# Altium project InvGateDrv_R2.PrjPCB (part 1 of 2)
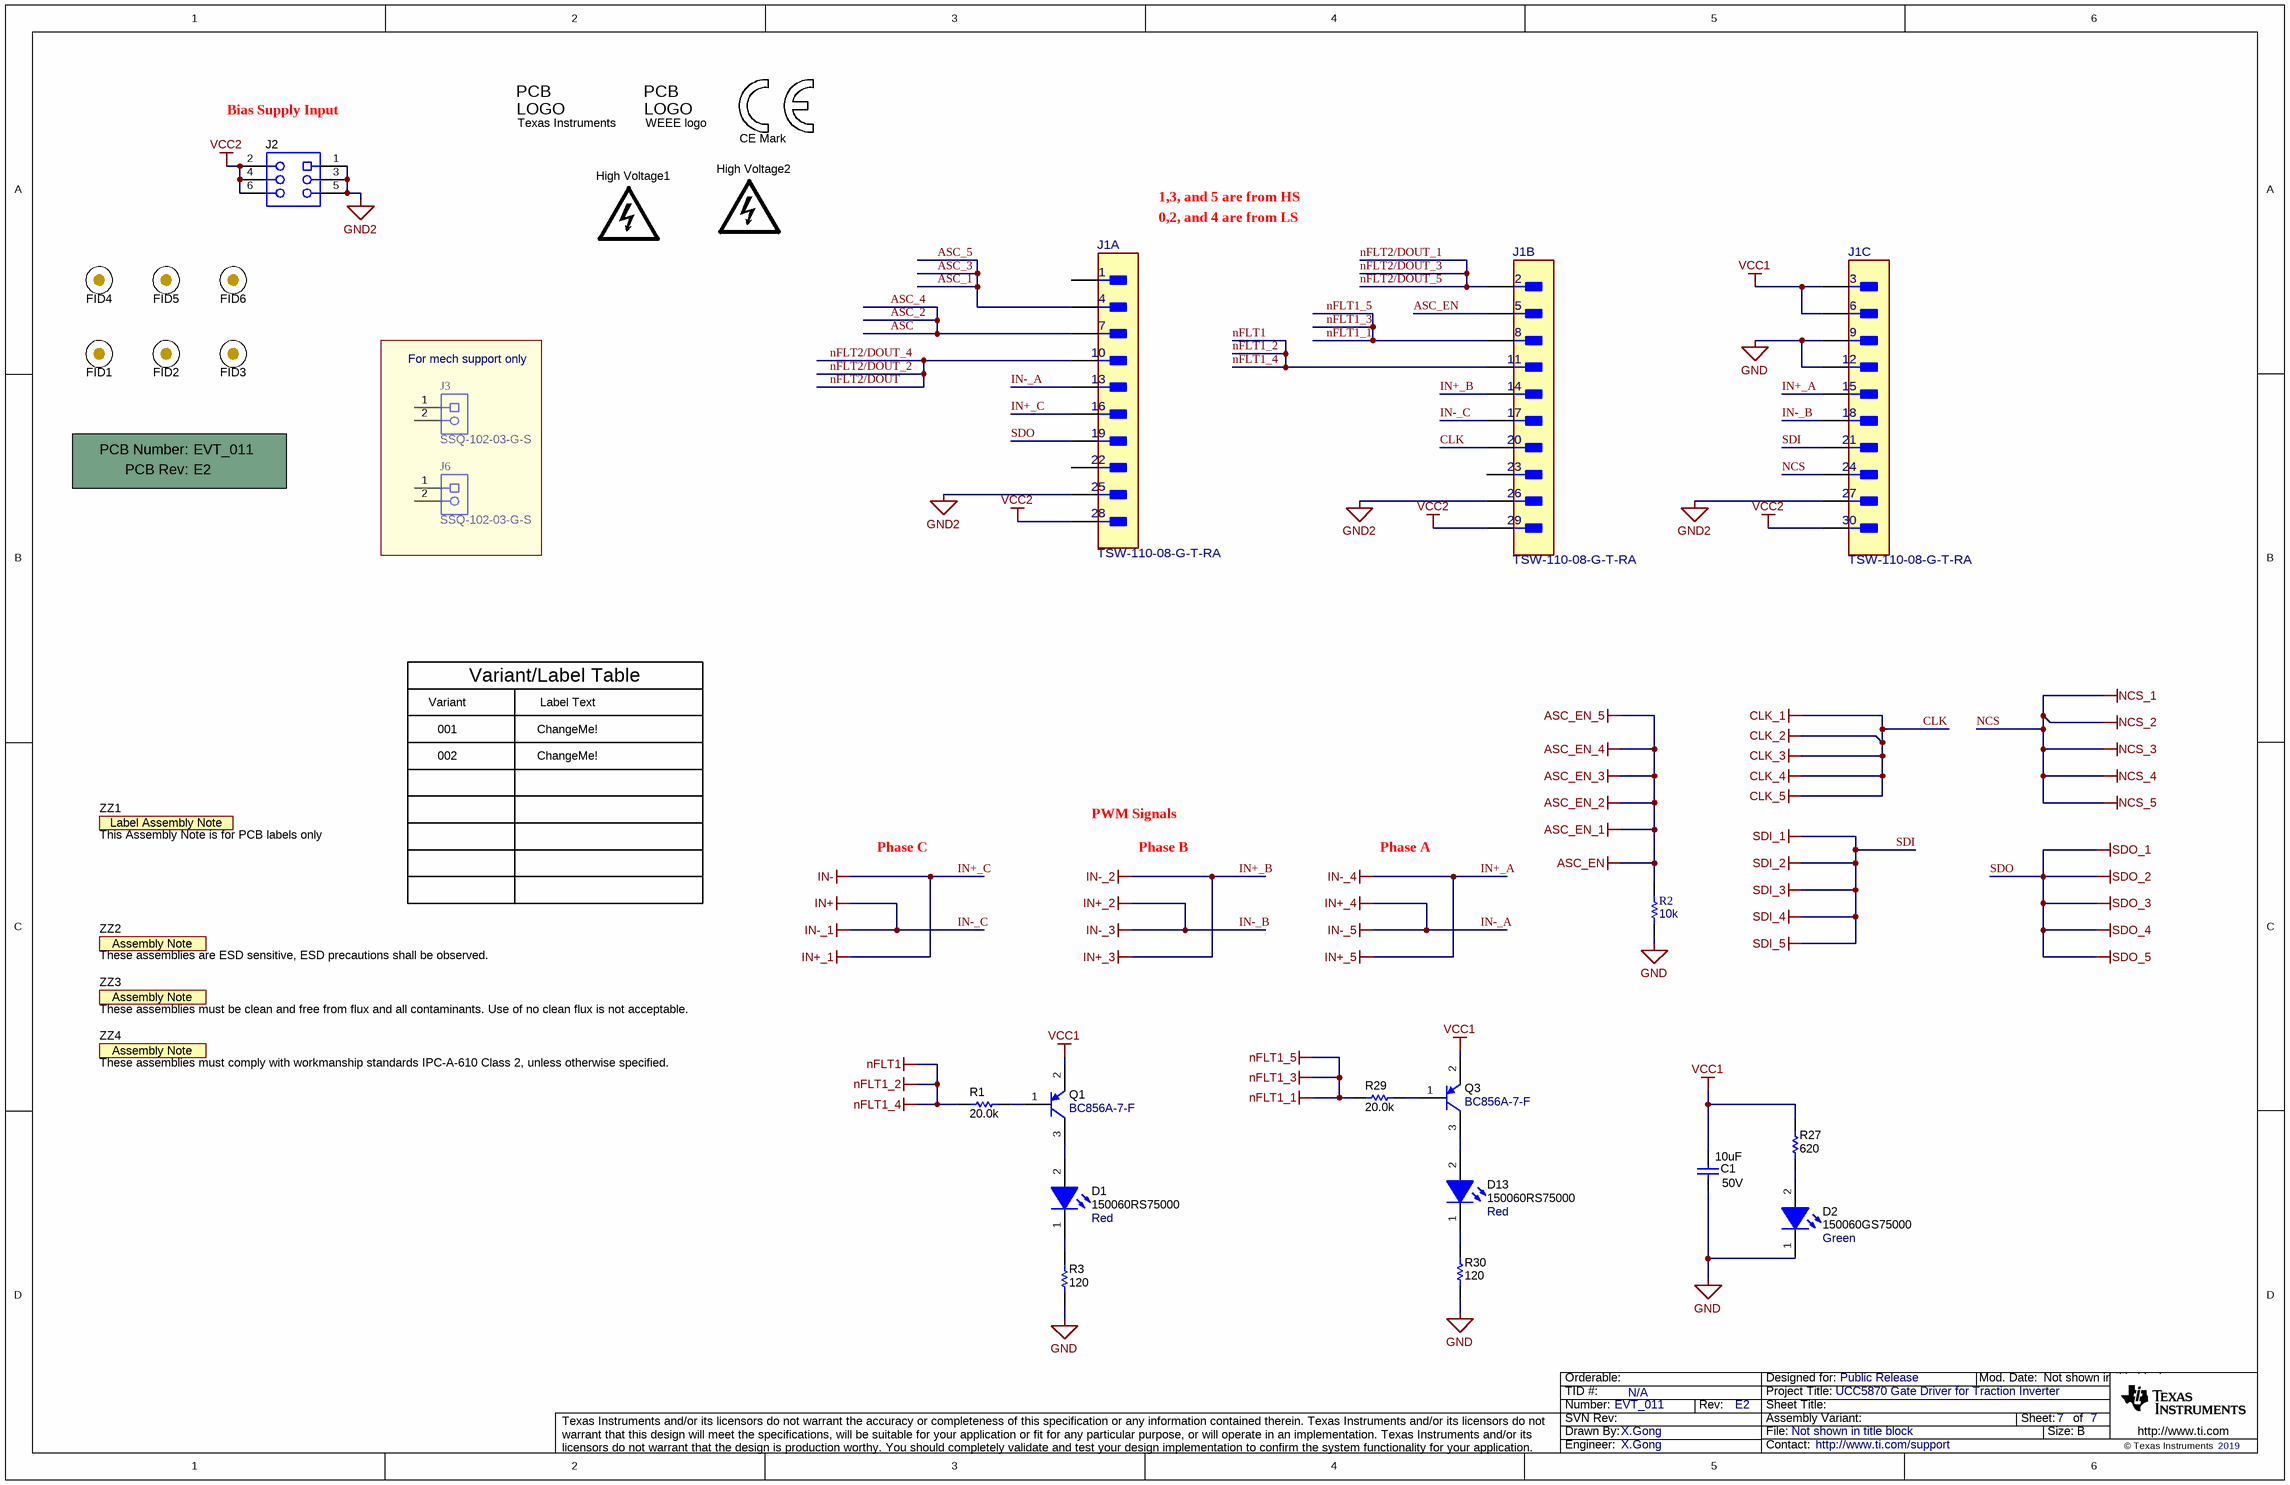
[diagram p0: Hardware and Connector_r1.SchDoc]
CopyrightYear: 2019; PCB_Layout: X. Gong; PCB_Rev: E2; PRJ_Customer: Public Release; PRJ_Engineer: X.Gong; PRJ_Number: EVT_011; PRJ_Title: UCC5870 Gate Driver for Traction Inverter; SCH_Rev: E2; TechSupport: http://www.ti.com/support; TID: N/A
7 sheets, 411 parts. Net scope: global (net labels, ports and power ports of the same name join across sheets).
Board file: InvGateDrv_R2_r3.PcbDoc
Sheets:
  Hardware and Connector_r1.SchDoc
  InvGateDriver_1.SchDoc
  InvGateDriver_2.SchDoc
  InvGateDriver_3.SchDoc
  InvGateDriver_4.SchDoc
  InvGateDriver_5.SchDoc
  InvGateDriver_6.SchDoc

## Sheet Hardware and Connector_r1.SchDoc
size 431 x 279 mm; Date: Not shown in title block; ApprovedBy: Not shown in title block; CheckedBy: Not shown in title block; Author: Not shown in title block; CompanyName: Not shown in title block; DrawnBy: X.Gong; Engineer: Not shown in title block; Organization: Not shown in title block; Address1: Not shown in title block; Address2: Not shown in title block; Address3: Not shown in title block; Address4: Not shown in title block; DocumentNumber: 3; Revision: Use project parameter SCH_Rev; SheetNumber: 7; SheetTotal: 7; PageSetup: Record=PageOptions¦CenterHorizontal=True¦CenterVertical=True¦PrintScale=1.00¦XCorrection=1.00¦YCorrection=1.00¦PrintKind=0¦BorderSize=5000000¦LeftOffset=0¦BottomOffset=0¦Orientation=2¦PaperLength=1000¦PaperWidth=1000¦Scale=100¦PaperSource=15¦PrintQuality=600¦MediaType=1¦DitherType=10¦PaperKind=Letter¦PrintScaleMode=1

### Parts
!PCB1  Printed Circuit Board  (value not drawn)  (mechanical)
C1  VDC_V: 50V  ValueDisplayed: 10uF  [1206_180]  (hidden comment: C3216X5R1H106K160AB)
D1  150060RS75000  value Red  [WL-SMCW_RED]
D2  150060GS75000  value Green  [WL-SMCW_GREEN]
D13  150060RS75000  value Red  [WL-SMCW_RED]
FID1  Fiducial  [Fiducial10-20]  (value not drawn)
FID2  Fiducial  [Fiducial10-20]  (value not drawn)
FID3  Fiducial  [Fiducial10-20]  (value not drawn)
FID4  Fiducial  [Fiducial10-20]  (value not drawn)
FID5  Fiducial  [Fiducial10-20]  (value not drawn)
FID6  Fiducial  [Fiducial10-20]  (value not drawn)
High_Voltage1  DANGER HIGH VOLTAGE  [IEC_HighVoltage_Small]  (value not drawn)  (no BOM)
High_Voltage2  DANGER HIGH VOLTAGE  [IEC_HighVoltage_Small]  (value not drawn)  (no BOM)
J1  TSW-110-08-G-T-RA  [FP-TSW-110-08-G-T-RA_HDR30-MFG]  (parts A,B,C of 3)
J2  PPPC032LFBN-RC  [Sullins_xxxC032LFBN-RC]  (value not drawn)
J3  SSQ-102-03-G-S  [Samtec_SSQ-102-03-x-S]
J6  SSQ-102-03-G-S  [Samtec_SSQ-102-03-x-S]
Logo1  CE Mark  [CE_Mark_5mm]  (no BOM)
Logo2  Texas Instruments  [TI_Stacked_Overlay_Small]  (no BOM)
Logo3  WEEE logo  [WEEE_Minimum]  (no BOM)
Q1  BC856A-7-F  [SOT-23]
Q3  BC856A-7-F  [SOT-23]
R1  ValueDisplayed: 20.0k  [0603]  (hidden comment: ERJ-3EKF2002V)
R2  ValueDisplayed: 10k  [0603]  (hidden comment: CRCW060310K0JNEA)
R3  ValueDisplayed: 120  [0402]  (hidden comment: CRCW0402120RJNED)
R27  ValueDisplayed: 620  [0603]  (hidden comment: RC0603FR-07620RL)
R29  ValueDisplayed: 20.0k  [0603]  (hidden comment: ERJ-3EKF2002V)
R30  ValueDisplayed: 120  [0402]  (hidden comment: CRCW0402120RJNED)
ZZ1  This Assembly Note is for PCB labels only  [AssemblyNoteLabel]  (no BOM)
ZZ2  These assemblies are ESD sensitive, ESD precautions shall be observed.  [AssemblyNote]  (no BOM)
ZZ3  These assemblies must be clean and free from flux and all contaminants. Use of no clean flux is not acceptable.  [AssemblyNote]  (no BOM)
ZZ4  These assemblies must comply with workmanship standards IPC-A-610 Class 2, unless otherwise specified.  [AssemblyNote]  (no BOM)

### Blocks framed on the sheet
For mech support only: J3 J6

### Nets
ASC: J1.7  [also labelled ASC_2, ASC_4]
ASC_1: J1.4  [also labelled ASC_3, ASC_5]
ASC_EN: J1.5 R2.2  [also labelled ASC_EN_1, ASC_EN_2, ASC_EN_3, ASC_EN_4, ASC_EN_5]
CLK: J1.20  [also labelled CLK_1, CLK_2, CLK_3, CLK_4, CLK_5]
GND: C1.2 D2.1(K) J1.9 J1.12 R2.1 R3.1 R30.1
GND2: J1.25 J1.26 J1.27 J2.1 J2.3 J2.5
IN+_A: J1.15  [also labelled IN+_5, IN-_4]
IN+_B: J1.14  [also labelled IN+_3, IN-_2]
IN+_C: J1.16  [also labelled IN+_1, IN-]
IN-_A: J1.13  [also labelled IN+_4, IN-_5]
IN-_B: J1.18  [also labelled IN+_2, IN-_3]
IN-_C: J1.17  [also labelled IN+, IN-_1]
NCS: J1.24  [also labelled NCS_1, NCS_2, NCS_3, NCS_4, NCS_5]
nFLT1: J1.11 R1.1  [also labelled nFLT1_2, nFLT1_4]
nFLT1_1: J1.8 R29.1  [also labelled nFLT1_3, nFLT1_5]
nFLT2/DOUT: J1.10  [also labelled nFLT2/DOUT_2, nFLT2/DOUT_4]
nFLT2/DOUT_1: J1.2  [also labelled nFLT2/DOUT_3, nFLT2/DOUT_5]
SDI: J1.21  [also labelled SDI_1, SDI_2, SDI_3, SDI_4, SDI_5]
SDO: J1.19  [also labelled SDO_1, SDO_2, SDO_3, SDO_4, SDO_5]
VCC1: C1.1 J1.3 J1.6 Q1.2(E) Q3.2(E) R27.2
VCC2: J1.28 J1.29 J1.30 J2.2 J2.4 J2.6
NetD1_1: D1.1(K) R3.2
NetD1_2: D1.2(A) Q1.3(C)
NetD2_2: D2.2(A) R27.1
NetD13_1: D13.1(K) R30.2
NetD13_2: D13.2(A) Q3.3(C)
NetQ1_1: Q1.1(B) R1.2
NetQ3_1: Q3.1(B) R29.2

Not connected (* = marked no-connect by the designer): J1 1 22 23; J3 1 2; J6 1 2

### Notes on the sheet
- (near J2) Bias Supply Input
- 1,3, and 5 are from HS
- 0,2, and 4 are from LS
- Variant
- Variant/Label Table
- Label Text
- 001
- 002
- ChangeMe!
- PWM Signals
- Phase C
- Phase B
- Phase A

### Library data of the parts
!PCB1 = CMP-0003618-2: Manufacturer: Any; PartNumber: EVT_011
C1 = CMP-0008658-2: CAP, CERM, 10 uF, 50 V, +/- 10%, X5R, 1206; Manufacturer: TDK; TaMin_C: -55°C; ESR_ohm: 2.229m; Polarized: N; SizeAreaWB_mm2: 10.92; Value1: 0.002229 ohm; U/M: EA; Value: 10uF; TaMax_C: 85°C; SizeZ_mm: 1.8; SizeX_mm: 3.2; SizeY_mm: 1.6; SizeArea_mm2: 5.12; Cap_F: 10µF; IRMS_A: 4.85932A; AEC Category: Q200
D1 D13 = CMP-0002947-3: LED, Red, SMD; Manufacturer: Wurth Elektronik; Type: AlInGaP; Vf_V: 2V; Io_A: 30mA; Vr_V: 5V; Tjmax_C: 85°C; Power_TotalModule: 72mW; Value1: 0.072W; Angle: 140
D2 = CMP-0002905-2: LED, Green, SMD; Manufacturer: Wurth Elektronik; Type: InGaN; Vf_V: 3.2V; Io_A: 20mA; Tjmax_C: 85°C; Value1: W; Angle: 140
FID1-FID6 = CMP-0077181-1: Fiducial mark.  There is nothing to buy or mount.
High_Voltage1 High_Voltage2 = CMP-0074835-1: IEC 61010-1 High Voltage Warning; SymbolCreator: a0412235
J1 = CMP-0088701-1: Conn Unshrouded Header HDR 30 POS 2.54mm Solder RA Thru-Hole Automotive Bulk; Manufacturer: Samtec; Current_A: 6.3A; Conn Orientation: Right Angle; AEC Qualified: No; Voltage_V: 450V; ContactFinish: Gold,Nickel; Conn Gender: Male; Row_Count: 3; SizeZ_mm: 8.26mm
J2 = CMP-0082513-1: Receptacle, 2.54mm, 3x2, Gold, TH; Manufacturer: Sullins Connector Solutions; Pitch_mm: 2.54; Gender: Female; Cert_UL: Y; Voltage_V: 250V; Current_A: 3A; Row_Count: 2; CompType: Socket Strip
J3 J6 = CMP-0055684-1: Receptacle, 2.54mm, 2x1, Gold, TH; Manufacturer: Samtec; CNHeader: FALSE; Current_A: 6.3A; Gender: Female; Cert_CSA: Y; CompType: Socket Strip; Row_Count: 1; Pitch_mm: 2.54; CT: TRUE
Logo1 = CMP-0074844-1: SymbolCreator: a0412235
Logo2 = CMP-0074838-1: Texas Instrument Corporate Signature; SymbolCreator: a0412235; Lib Reference: TI_Logo; Library Reference: Logo
Logo3 = CMP-0074769-1
Q1 Q3 = CMP-0000314-2: Transistor, PNP, 65 V, 0.01 A, SOT-23; Manufacturer: Diodes Inc.; CompType: BJT; PNP: 1; NPN: 0; Vceo_V: 65V; Vcesat1_V: 300mV; Value: 65 V; IcRated_A: 10mA; Value1: 0.01 A; TaMin_C: -65°C; TaMax_C: 150°C; SizeAreaWB_mm2: 14; SizeArea_mm2: 7.5; SizeX_mm: 2.5; SizeY_mm: 3; SizeZ_mm: 1.1; U/M: EA; AEC Category: Q101
R1 R29 = CMP-0022691-3: RES, 20.0 k, 1%, 0.1 W, AEC-Q200 Grade 0, 0603; Manufacturer: Panasonic; Value: 20.0k; Res_ohm: 20k; Value_Code: 20k0; Power_W: 100mW; Value2: 0.1W; VDC_V: 75V; TempCo: 100 ppm/C; SizeArea_mm2: 1.28; SizeX_mm: 1.6; SizeY_mm: 0.8; SizeZ_mm: 1; EIA_Code: E96; AEC Category: Q200; AEC Qualified: Y; AEC Grade: 0; U/M: EA
R2 = CMP-0025701-4: RES, 10 k, 5%, 0.1 W, AEC-Q200 Grade 0, 0603; Manufacturer: Vishay-Dale; Power_W: 100mW; TempCo: 200 ppm/C; Value_Code: 10k0; Value: 10k; EIA_Code: E24; SizeX_mm: 1.6; SizeY_mm: 0.8; SizeZ_mm: 1; Value2: 0.1W; SizeArea_mm2: 1.28; AEC Qualified: Y; VDC_V: 75V; AEC Category: Q200; AEC Grade: 0
R3 R30 = CMP-0026833-3: RES, 120, 5%, 0.063 W, AEC-Q200 Grade 0, 0402; Manufacturer: Vishay-Dale; Power_W: 63mW; TempCo: 200 ppm/C; Value_Code: 120R; Value: 120; EIA_Code: E24; SizeX_mm: 1; SizeY_mm: 0.5; SizeZ_mm: 0.6; Value2: 0.063W; AEC Qualified: Y; VDC_V: 50V; AEC Category: Q200; AEC Grade: 0
R27 = CMP-0023219-5: RES, 620, 1%, 0.1 W, 0603; Manufacturer: Yageo; Value: 620; Value_Code: 620R; Power_W: 100mW; Value2: 0.1W; VDC_V: 75V; TempCo: 100 ppm/C; SizeArea_mm2: 1.28; SizeX_mm: 1.6; SizeY_mm: 0.8; SizeZ_mm: 1; AEC Category: Q200; AEC Qualified: N; SizeAreaWB_mm2: 4.68
ZZ1 = CMP-0003616-3
ZZ2 = CMP-0077236-1
ZZ3 = CMP-0077237-1
ZZ4 = CMP-0077238-1

## Sheet InvGateDriver_1.SchDoc
size 431 x 279 mm; Date: Not shown in title block; ApprovedBy: Not shown in title block; CheckedBy: Not shown in title block; Author: Not shown in title block; CompanyName: Not shown in title block; DrawnBy: X.Gong; Engineer: Not shown in title block; Organization: Not shown in title block; Address1: Not shown in title block; Address2: Not shown in title block; Address3: Not shown in title block; Address4: Not shown in title block; DocumentNumber: 1; Revision: Use project parameter SCH_Rev; SheetNumber: 1; SheetTotal: 7; PageSetup: Record=PageOptions¦CenterHorizontal=True¦CenterVertical=True¦PrintScale=1.00¦XCorrection=1.00¦YCorrection=1.00¦PrintKind=0¦BorderSize=5000000¦LeftOffset=0¦BottomOffset=0¦Orientation=2¦PaperLength=1000¦PaperWidth=1000¦Scale=100¦PaperSource=15¦PrintQuality=600¦MediaType=1¦DitherType=10¦PaperKind=Letter¦PrintScaleMode=1
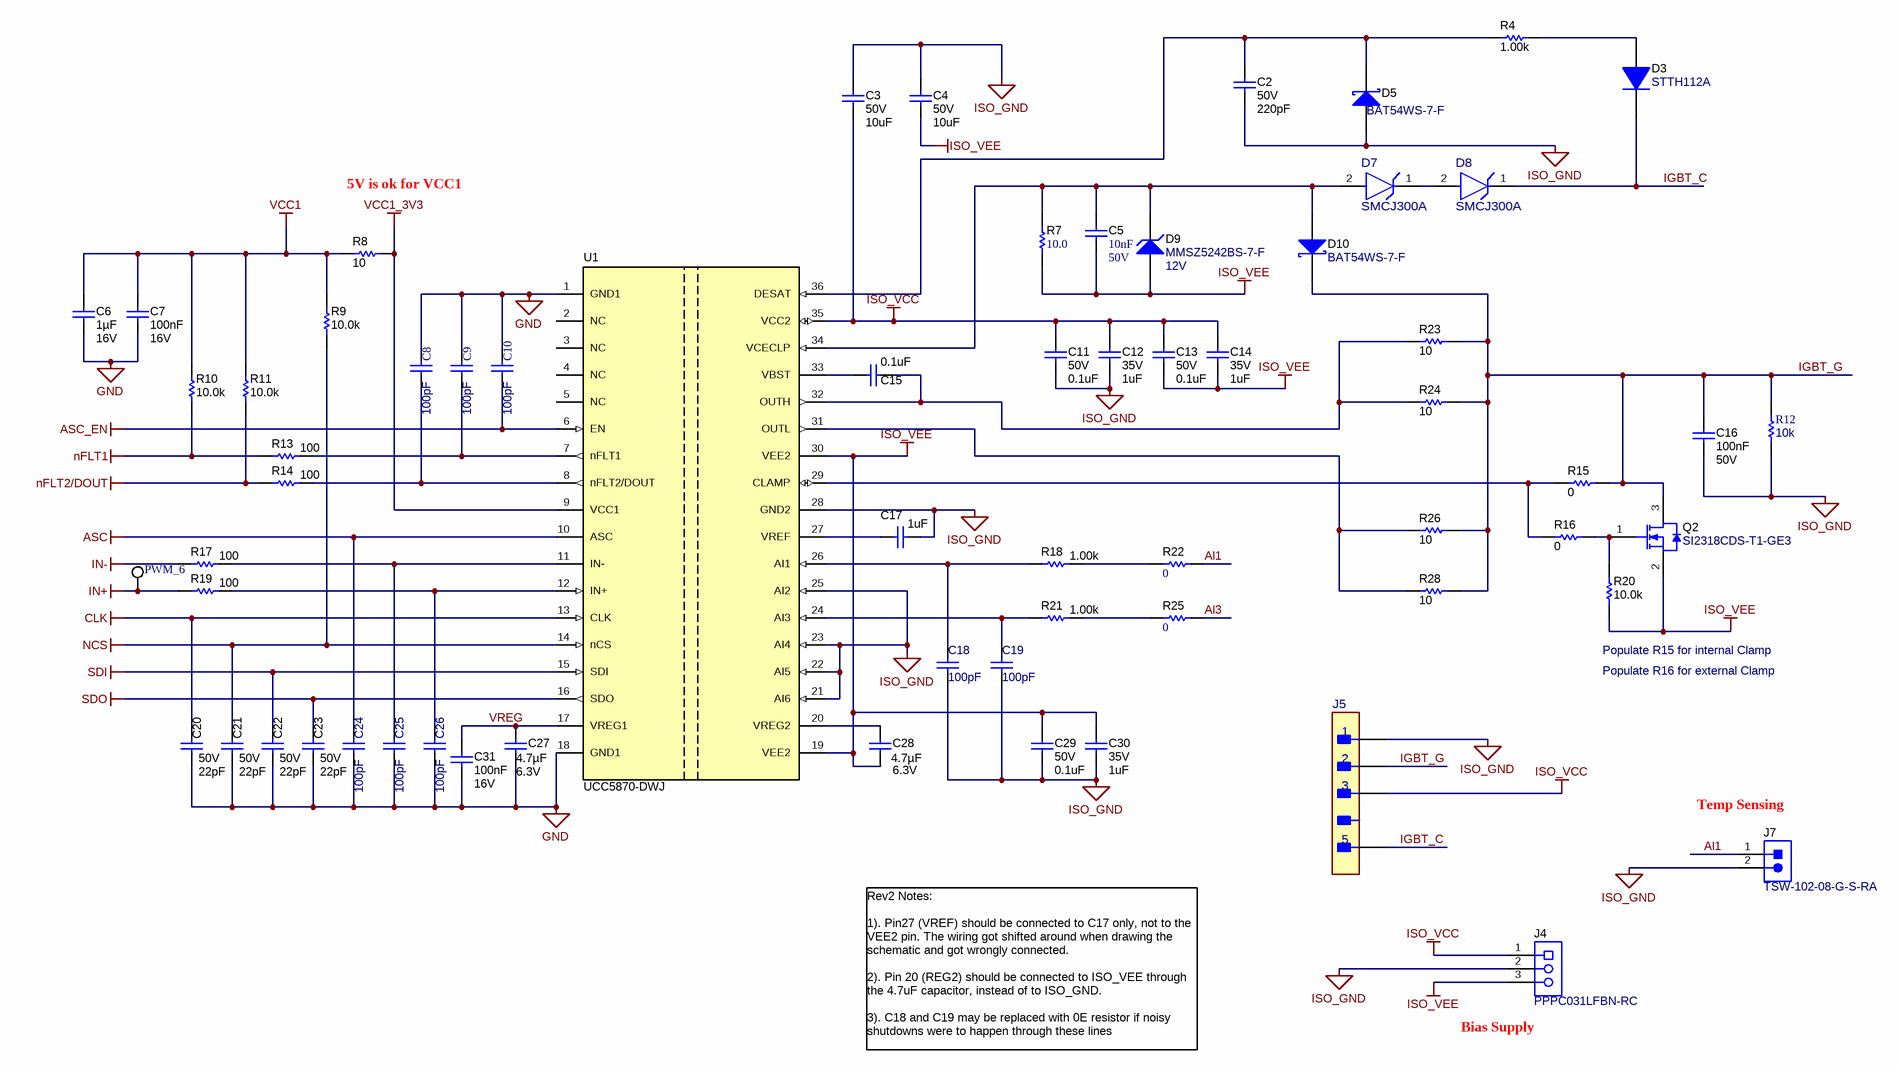
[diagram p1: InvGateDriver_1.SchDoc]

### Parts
C2  VDC_V: 50V  ValueDisplayed: 220pF  [0603]  (hidden comment: GRM188R71H221KA01D)
C3  VDC_V: 50V  ValueDisplayed: 10uF  [1206_180]  (hidden comment: CL31B106KBHNNNE)
C4  VDC_V: 50V  ValueDisplayed: 10uF  [1206_180]  (hidden comment: CL31B106KBHNNNE)
C5  Cap_F: 10nF  VDC_V: 50V  [0603]  (hidden comment: GRM188R71H103KA01D)
C6  Cap_F: 1µF  VDC_V: 16V  [0603]  (hidden comment: GCM188R71C105MA64D)
C7  Cap_F: 100nF  VDC_V: 16V  [0603]  (hidden comment: CGJ3E2X7R1C104K080AA)
C8  ValueDisplayed: 100pF  [0603]  (hidden comment: GCM1885C1H101JA16J)
C9  ValueDisplayed: 100pF  [0603]  (hidden comment: GCM1885C1H101JA16J)
C10  ValueDisplayed: 100pF  [0603]  (hidden comment: GCM1885C1H101JA16J)
C11  VDC_V: 50V  ValueDisplayed: 0.1uF  [0603]  (hidden comment: C1608X5R1H104K080AA)
C12  VDC_V: 35V  ValueDisplayed: 1uF  [0603]  (hidden comment: CGA3E1X7R1V105K080AC)
C13  VDC_V: 50V  ValueDisplayed: 0.1uF  [0603]  (hidden comment: C1608X5R1H104K080AA)
C14  VDC_V: 35V  ValueDisplayed: 1uF  [0603]  (hidden comment: CGA3E1X7R1V105K080AC)
C15  ValueDisplayed: 0.1uF  [0603]  (hidden comment: C1608X5R1H104K080AA)
C16  Cap_F: 100nF  VDC_V: 50V  [0805_HV]  (hidden comment: C0805C104K5RACAUTO)
C17  ValueDisplayed: 1uF  [0603]  (hidden comment: CGA3E1X7R1V105K080AC)
C18  ValueDisplayed: 100pF  [0603]  (hidden comment: GCM1885C1H101JA16J)
C19  ValueDisplayed: 100pF  [0603]  (hidden comment: GCM1885C1H101JA16J)
C20  VDC_V: 50V  ValueDisplayed: 22pF  [0603]  (hidden comment: CGA3E2C0G1H220J080AA)
C21  VDC_V: 50V  ValueDisplayed: 22pF  [0603]  (hidden comment: CGA3E2C0G1H220J080AA)
C22  VDC_V: 50V  ValueDisplayed: 22pF  [0603]  (hidden comment: CGA3E2C0G1H220J080AA)
C23  VDC_V: 50V  ValueDisplayed: 22pF  [0603]  (hidden comment: CGA3E2C0G1H220J080AA)
C24  ValueDisplayed: 100pF  [0603]  (hidden comment: GCM1885C1H101JA16J)
C25  ValueDisplayed: 100pF  [0603]  (hidden comment: GCM1885C1H101JA16J)
C26  ValueDisplayed: 100pF  [0603]  (hidden comment: GCM1885C1H101JA16J)
C27  Cap_F: 4.7µF  VDC_V: 6.3V  [0603]  (hidden comment: CL10B475KQ8NQND)
C28  Cap_F: 4.7µF  VDC_V: 6.3V  [0603]  (hidden comment: CL10B475KQ8NQND)
C29  VDC_V: 50V  ValueDisplayed: 0.1uF  [0603]  (hidden comment: C1608X5R1H104K080AA)
C30  VDC_V: 35V  ValueDisplayed: 1uF  [0603]  (hidden comment: CGA3E1X7R1V105K080AC)
C31  Cap_F: 100nF  VDC_V: 16V  [0603]  (hidden comment: CGJ3E2X7R1C104K080AA)
D3  STTH112A  [SMA]
D5  BAT54WS-7-F  [SOD-323]
D7  SMCJ300A  [FP-SMCJ300A_DO214AB-MFG]
D8  SMCJ300A  [FP-SMCJ300A_DO214AB-MFG]
D9  MMSZ5242BS-7-F  value 12V  [SOD-323]
D10  BAT54WS-7-F  [SOD-323]
J4  PPPC031LFBN-RC  [Sullins_PPPC031LFBN-RC]
J5  TSW-105-08-G-S-RA-004  [FP-TSW-105-08-G-S-RA-004_HDR4-MFG]  (value not drawn)
J7  TSW-102-08-G-S-RA  [TSW-102-08-G-S-RA]
PWM_6  5002  [Keystone5002]  (value not drawn)
Q2  SI2318CDS-T1-GE3  [SOT-23]
R4  ValueDisplayed: 1.00k  [0603]  (hidden comment: CRCW06031K00FKEA)
R7  ValueDisplayed: 10.0  [0805_HV]  (hidden comment: CRCW080510R0FKEA)
R8  ValueDisplayed: 10  [0805_HV]  (hidden comment: CRCW080510R0JNEA)
R9  ValueDisplayed: 10.0k  [0603]  (hidden comment: ERJ-3EKF1002V)
R10  ValueDisplayed: 10.0k  [0603]  (hidden comment: ERJ-3EKF1002V)
R11  ValueDisplayed: 10.0k  [0603]  (hidden comment: ERJ-3EKF1002V)
R12  ValueDisplayed: 10k  [0603]  (hidden comment: CRCW060310K0JNEA)
R13  ValueDisplayed: 100  [0603]  (hidden comment: CRCW0603100RJNEA)
R14  ValueDisplayed: 100  [0603]  (hidden comment: CRCW0603100RJNEA)
R15  ValueDisplayed: 0  [0805_HV]  (hidden comment: CRCW08050000Z0EA)
R16  ValueDisplayed: 0  [0805_HV]  (hidden comment: CRCW08050000Z0EA)
R17  ValueDisplayed: 100  [0603]  (hidden comment: CRCW0603100RJNEA)
R18  ValueDisplayed: 1.00k  [0603]  (hidden comment: CRCW06031K00FKEA)
R19  ValueDisplayed: 100  [0603]  (hidden comment: CRCW0603100RJNEA)
R20  ValueDisplayed: 10.0k  [0603]  (hidden comment: RCG060310K0FKEA)
R21  ValueDisplayed: 1.00k  [0603]  (hidden comment: CRCW06031K00FKEA)
R22  ValueDisplayed: 0  [0603]  (hidden comment: CRCW06030000Z0EA)
R23  ValueDisplayed: 10  [2010]  (hidden comment: CRCW201010R0JNEF)
R24  ValueDisplayed: 10  [2010]  (hidden comment: CRCW201010R0JNEF)
R25  ValueDisplayed: 0  [0603]  (hidden comment: CRCW06030000Z0EA)
R26  ValueDisplayed: 10  [2010]  (hidden comment: CRCW201010R0JNEF)
R28  ValueDisplayed: 10  [2010]  (hidden comment: CRCW201010R0JNEF)
U1  UCC5870-DWJ  [DWJ0036A]

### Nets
ASC: C24.1 U1.10(ASC)
ASC_EN: C10.2 U1.6(EN)
CLK: C20.1 U1.13(CLK)
GND: C6.2 C7.2 C8.1 C9.1 C10.1 C20.2 C21.2 C22.2 C23.2 C24.2 C25.2 C26.2 C27.2 C31.2 U1.1(GND1) U1.18(GND1)
IN+: PWM_6.1 R19.1  [project net IN-_C]
IN-: R17.1  [project net IN+_C]
ISO_GND: C2.1 C3.1 C4.1 C11.2 C12.2 C16.2 C17.2 C18.2 C19.2 C29.2 C30.1 D5.2(A) J4.2 J5.1 J7.2 R12.1 U1.21(AI6) U1.22(AI5) U1.23(AI4) U1.25(AI2) U1.28(GND2)
ISO_VCC: C3.2 C11.1 C12.1 C13.1 C14.1 J4.1 J5.3 U1.35(VCC2)
ISO_VEE: C4.2 C5.2 C13.2 C14.2 C28.2 C29.1 C30.2 D9.2(A) J4.3 Q2.2(S) R7.1 R20.1 U1.19(VEE2) U1.30(VEE2)
NCS: C21.1 R9.1 U1.14(nCS)
nFLT1: R10.2 R13.1
nFLT2/DOUT: R11.1 R14.1
SDI: C22.1 U1.15(SDI)
SDO: C23.1 U1.16(SDO)
VCC1: C6.1 C7.1 R8.1 R9.2 R10.1 R11.2
VCC1_3V3: R8.2 U1.9(VCC1)
Al1: J7.1 R22.2
Al3: R25.2
IGBT_C: D3.1(K) D8.1(CATHODE) J5.5
IGBT_G: C16.1 D10.1(K) J5.2 Q2.3(D) R12.2 R15.1 R23.2 R24.2 R26.2 R28.2
VREG: C27.1 C31.1 U1.17(VREG1)
NetC2_2: C2.2 D5.1(K) R4.1 U1.36(DESAT)
NetC5_1: C5.1 D7.2(ANODE) D9.1(K) D10.2(A) R7.2 U1.34(VCECLP)
NetC8_2: C8.2 R14.2 U1.8(nFLT2/DOUT)
NetC9_2: C9.2 R13.2 U1.7(nFLT1)
NetC15_1: C15.1 U1.33(VBST)
NetC15_2: C15.2 R23.1 R24.1 U1.32(OUTH)
NetC17_1: C17.1 U1.27(VREF)
NetC18_1: C18.1 R18.1 U1.26(AI1)
NetC19_1: C19.1 R21.1 U1.24(AI3)
NetC25_1: C25.1 R17.2 U1.11(IN-)
NetC26_1: C26.1 R19.2 U1.12(IN+)
NetC28_1: C28.1 U1.20(VREG2)
NetD3_2: D3.2(A) R4.2
NetD7_1: D7.1(CATHODE) D8.2(ANODE)
NetQ2_1: Q2.1(G) R16.1 R20.2
NetR15_2: R15.2 R16.2 U1.29(CLAMP)
NetR18_2: R18.2 R22.1
NetR21_2: R21.2 R25.1
NetR26_1: R26.1 R28.1 U1.31(OUTL)

Not connected (* = marked no-connect by the designer): U1 2(NC) 3(NC) 4(NC) 5(NC)

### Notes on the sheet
- 5V is ok for VCC1
- (near R20) Populate R15 for internal Clamp
- Populate R16 for external Clamp
- (near J7) Temp Sensing
- Rev2 Notes:
  1). Pin27 (VREF) should be connected to C17 only, not to the VEE2 pin. The wiring got shifted around when drawing the schematic and got wrongly connected.
  2). Pin 20 (REG2) should be connected to ISO_VEE through the 4.7uF capacitor, instead of to ISO_GND.
  3). C18 and C19 may be replaced with 0E resistor if noisy shutdowns were to happen through these lines
- (near J4) Bias Supply

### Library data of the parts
C2 = CMP-0007442-5: CAP, CERM, 220 pF, 50 V, +/- 10%, X7R, 0603; Manufacturer: MuRata; TaMin_C: -55°C; Polarized: N; SizeAreaWB_mm2: 4.68; Value1: Unknown; U/M: EA; Value: 220pF; TaMax_C: 125°C; SizeZ_mm: 1; SizeX_mm: 1.6; SizeY_mm: 0.8; SizeArea_mm2: 1.28; AEC Category: Q200
C3 = CMP-0008802-2: CAP, CERM, 10 uF, 50 V, +/- 10%, X7R, 1206; Manufacturer: Samsung; TaMin_C: -55°C; Polarized: N; SizeAreaWB_mm2: 10.92; Value1: Unknown; U/M: EA; Value: 10uF; TaMax_C: 125°C; SizeZ_mm: 1.8; SizeX_mm: 3.2; SizeY_mm: 1.6; Cap_Case: 1206; SizeArea_mm2: 5.12; Cap_F: 10µF; AEC Category: Q200
C4 = CMP-0008802-2: CAP, CERM, 10 uF, 50 V, +/- 10%, X7R, 1206; Manufacturer: Samsung; TaMin_C: -55°C; Polarized: N; SizeAreaWB_mm2: 10.92; Value1: Unknown; U/M: EA; Value: 10uF; TaMax_C: 125°C; SizeZ_mm: 1.8; SizeX_mm: 3.2; SizeY_mm: 1.6; Cap_Case: 1206; SizeArea_mm2: 5.12; CompType: Capacitor; Cap_F: 10µF; AEC Category: Q200
C5 = CMP-0007433-4: CAP, CERM, 0.01 uF, 50 V, +/- 10%, X7R, 0603; Manufacturer: MuRata; TaMin_C: -55°C; Polarized: N; SizeAreaWB_mm2: 4.68; Value1: Unknown; U/M: EA; Value: 0.01uF; TaMax_C: 125°C; SizeZ_mm: 1; SizeX_mm: 1.6; SizeY_mm: 0.8; SizeArea_mm2: 1.28; AEC Category: Q200
C6 = CMP-0007137-5: CAP, CERM, 1 uF, 16 V, +/- 20%, X7R, AEC-Q200 Grade 1, 0603; Manufacturer: MuRata; TaMin_C: -55°C; Polarized: N; SizeAreaWB_mm2: 4.68; Value1: Unknown; U/M: EA; Value: 1uF; TaMax_C: 125°C; SizeZ_mm: 1; SizeX_mm: 1.6; SizeY_mm: 0.8; SizeArea_mm2: 1.28; AEC Qualified: Y; AEC Category: Q200
C7 = CMP-0007106-4: CAP, CERM, 0.1 uF, 16 V, +/- 10%, X7R, AEC-Q200 Grade 1, 0603; Manufacturer: TDK; TaMin_C: -55°C; Polarized: N; SizeAreaWB_mm2: 4.68; Value1: Unknown; U/M: EA; Value: 0.1uF; TaMax_C: 125°C; SizeZ_mm: 1; SizeX_mm: 1.6; SizeY_mm: 0.8; SizeArea_mm2: 1.28; AEC Qualified: Y; AEC Category: Q200
C8-C10 C18 C19 C24-C26 = CMP-0750041-1: CAP, CERM, 100 pF, 50 V,+/- 5%, C0G/NP0, AEC-Q200 Grade 1, 0603; Manufacturer: MuRata; AEC Grade: 1; SizeArea_mm2: 1.28; SizeX_mm: 1.6; Polarized: N; TaMax_C: 125°C; Value2: 50V; Value: 100pF; U/M: EA; CompType: Capacitor; AEC Qualified: Y; SizeAreaWB_mm2: 4.68; TaMin_C: -55°C; SizeY_mm: 0.8; AEC Category: Q200
C11 C29 = CMP-0007010-5: CAP, CERM, 0.1 uF, 50 V, +/- 10%, X5R, 0603; Manufacturer: TDK; TaMin_C: -55°C; ESR_ohm: 0.0296; Polarized: N; SizeAreaWB_mm2: 4.68; Value1: 0.0296 ohm; U/M: EA; Value: 0.1uF; TaMax_C: 85°C; SizeZ_mm: 1; SizeX_mm: 1.6; SizeY_mm: 0.8; SizeArea_mm2: 1.28; Cap_F: 100nF; IRMS_A: 9.7199dA; AEC Category: Q200
C12 C14 C30 = CMP-0007067-4: CAP, CERM, 1 uF, 35 V, +/- 10%, X7R, AEC-Q200 Grade 1, 0603; Manufacturer: TDK; TaMin_C: -55°C; ESR_ohm: 5.522m; Polarized: N; SizeAreaWB_mm2: 4.68; Value1: 0.005522 ohm; U/M: EA; Value: 1uF; TaMax_C: 125°C; SizeZ_mm: 1; SizeX_mm: 1.6; SizeY_mm: 0.8; SizeArea_mm2: 1.28; CompType: Capacitor; AEC Qualified: Y; Cap_F: 1µF; IRMS_A: 2.21617A; AEC Category: Q200
C13 = CMP-0007010-5: CAP, CERM, 0.1 uF, 50 V, +/- 10%, X5R, 0603; Manufacturer: TDK; TaMin_C: -55°C; ESR_ohm: 0.0296; Polarized: N; SizeAreaWB_mm2: 4.68; Value1: 0.0296 ohm; U/M: EA; Value: 0.1uF; TaMax_C: 85°C; SizeZ_mm: 1; SizeX_mm: 1.6; SizeY_mm: 0.8; SizeArea_mm2: 1.28; CompType: Capacitor; Cap_F: 100nF; IRMS_A: 9.7199dA; AEC Category: Q200
C15 = CMP-0007010-5: CAP, CERM, 0.1 uF, 50 V, +/- 10%, X5R, 0603; Manufacturer: TDK; TaMin_C: -55°C; ESR_ohm: 0.0296; Polarized: N; SizeAreaWB_mm2: 4.68; Value1: 0.0296 ohm; U/M: EA; Value: 0.1uF; TaMax_C: 85°C; SizeZ_mm: 1; SizeX_mm: 1.6; SizeY_mm: 0.8; Value2: 50V; SizeArea_mm2: 1.28; CompType: Capacitor; Cap_F: 100nF; IRMS_A: 9.7199dA; AEC Category: Q200
C16 = CMP-0007725-2: CAP, CERM, 0.1 uF, 50 V, +/- 10%, X7R, AEC-Q200 Grade 0, 0805; Manufacturer: Kemet; TaMin_C: -55°C; Polarized: N; SizeAreaWB_mm2: 6.75; Value1: Unknown; U/M: EA; Value: 0.1uF; TaMax_C: 125°C; SizeZ_mm: 1.45; SizeX_mm: 2; SizeY_mm: 1.25; Cap_Case: 0805; SizeArea_mm2: 2.5; AEC Qualified: Y; AEC Grade: 0; AEC Category: Q200
C17 = CMP-0007067-4: CAP, CERM, 1 uF, 35 V, +/- 10%, X7R, AEC-Q200 Grade 1, 0603; Manufacturer: TDK; TaMin_C: -55°C; ESR_ohm: 5.522m; Polarized: N; SizeAreaWB_mm2: 4.68; Value1: 0.005522 ohm; U/M: EA; Value: 1uF; TaMax_C: 125°C; SizeZ_mm: 1; SizeX_mm: 1.6; SizeY_mm: 0.8; Value2: 35V; SizeArea_mm2: 1.28; CompType: Capacitor; AEC Qualified: Y; Cap_F: 1µF; IRMS_A: 2.21617A; AEC Category: Q200
C20-C23 = CMP-0007071-3: CAP, CERM, 22 pF, 50 V, +/- 5%, C0G/NP0, AEC-Q200 Grade 1, 0603; Manufacturer: TDK; TaMin_C: -55°C; Polarized: N; SizeAreaWB_mm2: 4.68; Value1: Unknown; U/M: EA; Value: 22pF; TaMax_C: 125°C; SizeZ_mm: 1; SizeX_mm: 1.6; SizeY_mm: 0.8; SizeArea_mm2: 1.28; AEC Qualified: Y; AEC Category: Q200
C27 C28 = CMP-0007112-4: CAP, CERM, 4.7 uF, 6.3 V, +/- 10%, X7R, 0603; Manufacturer: Samsung; TaMin_C: -55°C; Polarized: N; SizeAreaWB_mm2: 4.68; Value1: Unknown; U/M: EA; Value: 4.7uF; TaMax_C: 125°C; SizeZ_mm: 1; SizeX_mm: 1.6; SizeY_mm: 0.8; SizeArea_mm2: 1.28; CompType: Capacitor; AEC Category: Q200
C31 = CMP-0007106-4: CAP, CERM, 0.1 uF, 16 V, +/- 10%, X7R, AEC-Q200 Grade 1, 0603; Manufacturer: TDK; TaMin_C: -55°C; Polarized: N; SizeAreaWB_mm2: 4.68; Value1: Unknown; U/M: EA; Value: 0.1uF; TaMax_C: 125°C; SizeZ_mm: 1; SizeX_mm: 1.6; SizeY_mm: 0.8; SizeArea_mm2: 1.28; CompType: Capacitor; AEC Qualified: Y; AEC Category: Q200
D3 = CMP-0077081-2: Diode, Ultrafast, 1200 V, 1 A, SMA; Manufacturer: STMicroelectronics; SizeAreaWB_mm2: 37.3428; Vr_V: 1.2kV; SizeArea_mm2: 16.3228; AEC Qualified: N; TJmax_C: 175°C; AEC Category: Q101; Value: 1200V; SizeZ_mm: 2.87; Green_REACh: Incomplete; Io_A: 1A; Vf_V: 1.9V; SizeY_mm: 2.92; Green_Lifecycle: Not Set; SizeX_mm: 5.59
D5 D10 = CMP-0028458-2: Diode, Schottky, 30 V, 0.2 A, SOD-323; Manufacturer: Diodes Inc.; Io_A: 200mA; Green_Lifecycle: Active; SizeAreaWB_mm2: 8.695; Vr_V: 30V; Green_REACh: Passed; Value1: 0.2A; TJmax_C: 125°C; Value: 30V; SizeZ_mm: 1; SizeX_mm: 2.7; SizeY_mm: 1.35; Vf_V: 700mV; Value2: 0.7V; SizeArea_mm2: 3.645; AEC Category: Q101
D7 D8 = CMP-0088475-1: 486V Clamp 3.1A Ipp Tvs Diode Surface Mount DO-214AB (SMCJ); Manufacturer: Littelfuse Inc; Ppk: 1.5kW; VRWM: 300V; AEC Qualified: No; TJmax_C: +150°C; Number Of Channels: 1; Direction: Unidirectional; SizeZ_mm: 2.62mm; Breakdown Voltage: 335V
D9 = CMP-0005831-4: Diode, Zener, 12 V, 200 mW, SOD-323; Manufacturer: Diodes Inc.; Power_W: 200mW; SizeAreaWB_mm2: 8.695; Value1: 0.2W; RJA_CperW: 350; SizeZ_mm: 1; SizeX_mm: 2.7; SizeY_mm: 1.35; SizeArea_mm2: 3.645; AEC Category: Q101
J4 = CMP-0054646-1: Receptacle, 100mil, 3x1, Gold, TH; Manufacturer: Sullins Connector Solutions; CT: TRUE; CompType: Socket Strip; CNHeader: FALSE
J5 = CMP-0088430-1: THROUGH-HOLE .025" SQ POST HEADER; Manufacturer: Samtec; SizeZ_mm: 3.15mm; Row_Count: 1; Voltage_V: 550V; ContactFinish: Gold,Nickel; Conn Orientation: Right Angle; Conn Gender: Male; AEC Qualified: No; DUT-Pitch_mm: 2.54mm
J7 = CMP-0055976-1: Header, 100mil, 2x1, Gold, R/A, TH; Manufacturer: Samtec; Cert_VDE: N; CNHeader: FALSE; Current_A: 6.3A; Green_Lifecycle: Active; Gender: Male; Cert_CSA: Y; Green_REACh: Passed; Voltage_V: 550V; Row_Count: 1; Pitch_mm: 2.54
PWM_6 = CMP-0055139-1: Test Point, Miniature, White, TH; Manufacturer: Keystone; ContactFinish: Silver; Green_Lifecycle: Active; Green_REACh: Passed; CNHeader: FALSE; CT: TRUE
Q2 = CMP-0000739-1: MOSFET, N-CH, 40 V, 5.6 A, SOT-23; Alternate Manufacturer: None; Manufacturer: Vishay-Siliconix; SizeZ_mm: 1.1; ChType: N; Value2: 5.8 nC; Value1: 0.05; VdsMax_V: 40V; SizeX_mm: 2.5; SizeY_mm: 3; Vgs_V: 20V; Value: 40V; Rdson45_ohm: 0.051; SizeArea_mm2: 7.5; AEC Category: Q101; IdsMax_A: 5.6A; SizeAreaWB_mm2: 14; U/M: EA; QgTyp_nC: 5.8
R4 R18 R21 = CMP-0022109-5: RES, 1.00 k, 1%, 0.1 W, AEC-Q200 Grade 0, 0603; Manufacturer: Vishay-Dale; Power_W: 100mW; TempCo: 100 ppm/C; Value_Code: 1k00; Value: 1.00k; EIA_Code: E96; Res_ohm: 1k; SizeX_mm: 1.6; SizeY_mm: 0.8; SizeZ_mm: 1; Value2: 0.1W; SizeArea_mm2: 1.28; AEC Qualified: Y; VDC_V: 75V; AEC Category: Q200; AEC Grade: 0
R7 = CMP-0020847-3: RES, 10.0, 1%, 0.125 W, AEC-Q200 Grade 0, 0805; Manufacturer: Vishay-Dale; Power_W: 125mW; TempCo: 100 ppm/C; Value_Code: 10R0; Value: 10.0; EIA_Code: E96; Res_ohm: 10; SizeX_mm: 2; SizeY_mm: 1.25; SizeZ_mm: 1.45; Value2: 0.125W; SizeArea_mm2: 2.5; AEC Qualified: Y; VDC_V: 150V; AEC Category: Q200; AEC Grade: 0
R8 = CRCW080510R0JNEA: RES, 10, 5%, 0.125 W, 0805; Manufacturer: Vishay-Dale; CompType: Resistor; Value: 10; Value_Code: 10R0; Tolerance_%: 5; Power_W: 0.125; Value2: 0.125W; VDC_V: 150; TempCo: 200 ppm/C; SizeArea_mm2: 2.5; SizeX_mm: 2; SizeY_mm: 1.25; SizeZ_mm: 1.45; EIA_Code: E24; U/M: EA; AEC Category: Q200; Green_Lifecycle: Active; Green_REACh: Passed
R9-R11 = CMP-0022684-3: RES, 10.0 k, 1%, 0.1 W, 0603; Manufacturer: Panasonic; Power_W: 100mW; TempCo: 100 ppm/C; Value_Code: 10k0; U/M: EA; Value: 10.0k; EIA_Code: E96; Res_ohm: 10k; SizeX_mm: 1.6; SizeY_mm: 0.8; SizeZ_mm: 1; Value2: 0.1W; SizeArea_mm2: 1.28; VDC_V: 75V; AEC Category: Q200
R12 = CMP-0025701-4: as R2 on sheet Hardware and Connector_r1
R13 R14 R17 R19 = CMP-0025700-4: RES, 100, 5%, 0.1 W, AEC-Q200 Grade 0, 0603; Manufacturer: Vishay-Dale; Power_W: 100mW; TempCo: 200 ppm/C; Value_Code: 100R; Value: 100; EIA_Code: E24; SizeX_mm: 1.6; SizeY_mm: 0.8; SizeZ_mm: 1; Value2: 0.1W; SizeArea_mm2: 1.28; AEC Qualified: Y; VDC_V: 75V; AEC Category: Q200; AEC Grade: 0
R15 R16 = CRCW08050000Z0EA: RES, 0, 5%, 0.125 W, 0805; Manufacturer: Vishay-Dale; CompType: Resistor; Value: 0; Value_Code: 0000; Tolerance_%: 5; Power_W: 0.125; Value2: 0.125W; VDC_V: 150; TempCo: 200 ppm/C; SizeArea_mm2: 2.5; SizeX_mm: 2; SizeY_mm: 1.25; SizeZ_mm: 1.45; EIA_Code: E24; U/M: EA; AEC Category: Q200; Green_Lifecycle: Active; Green_REACh: Passed
R20 = RCG060310K0FKEA: RES, 10.0 k, 1%, 0.1 W, 0603; Manufacturer: Vishay Draloric; CompType: Resistor; Value: 10.0k; Res_ohm: 10000; Value_Code: 10k0; Tolerance_%: 1; Power_W: 0.1; Value2: 0.1W; VDC_V: 75; TempCo: 100 ppm/C; SizeArea_mm2: 1.28; SizeX_mm: 1.6; SizeY_mm: 0.8; EIA_Code: E96; U/M: EA; AEC Category: Q200; AEC Qualified: N
R22 R25 = CMP-0025697-4: RES, 0, 5%, 0.1 W, AEC-Q200 Grade 0, 0603; Manufacturer: Vishay-Dale; Power_W: 100mW; TempCo: 200 ppm/C; Value_Code: 0000; Value: 0; EIA_Code: E24; SizeX_mm: 1.6; SizeY_mm: 0.8; SizeZ_mm: 1; Value2: 0.1W; SizeArea_mm2: 1.28; AEC Qualified: Y; VDC_V: 75V; AEC Category: Q200
R23 R24 R26 R28 = CRCW201010R0JNEF: RES, 10, 5%, 0.75 W, AEC-Q200 Grade 0, 2010; Manufacturer: Vishay-Dale; CompType: Resistor; Value: 10; Value_Code: 10R0; Tolerance_%: 5; Power_W: 0.75; Value2: 0.75W; VDC_V: 400; TempCo: 200 ppm/C; SizeArea_mm2: 12.5; SizeY_mm: 2.5; SizeZ_mm: 1.66; EIA_Code: E24; U/M: EA; AEC Category: Q200; AEC Qualified: Y; AEC Grade: 0
U1 = CMP-0080759-3: Isolated IGBT, SiC MOSFET Gate Driver With Real-Time Programmability, DWJ0036A (SOIC-36); Alternate Manufacturer: Texas Instruments; SizeAreaWB_mm2: 182.04; SizeZ_mm: 3.55; SizeX_mm: 10.3; SizeY_mm: 12.8; SizeArea_mm2: 131.84; CompType: IC; AEC Qualified: N; AEC Category: Q200

## Sheet InvGateDriver_2.SchDoc
size A3; SheetNumber: 2; SheetTotal: 7; PageSetup: Record=PageOptions¦CenterHorizontal=True¦CenterVertical=True¦PrintScale=0.69¦XCorrection=1.00¦YCorrection=1.00¦PrintKind=0¦BorderSize=5000000¦LeftOffset=0¦BottomOffset=0¦Orientation=2¦PaperLength=1000¦PaperWidth=1000¦Scale=100¦PaperSource=15¦PrintQuality=600¦MediaType=1¦DitherType=10¦PaperKind=Letter¦PrintScaleMode=1
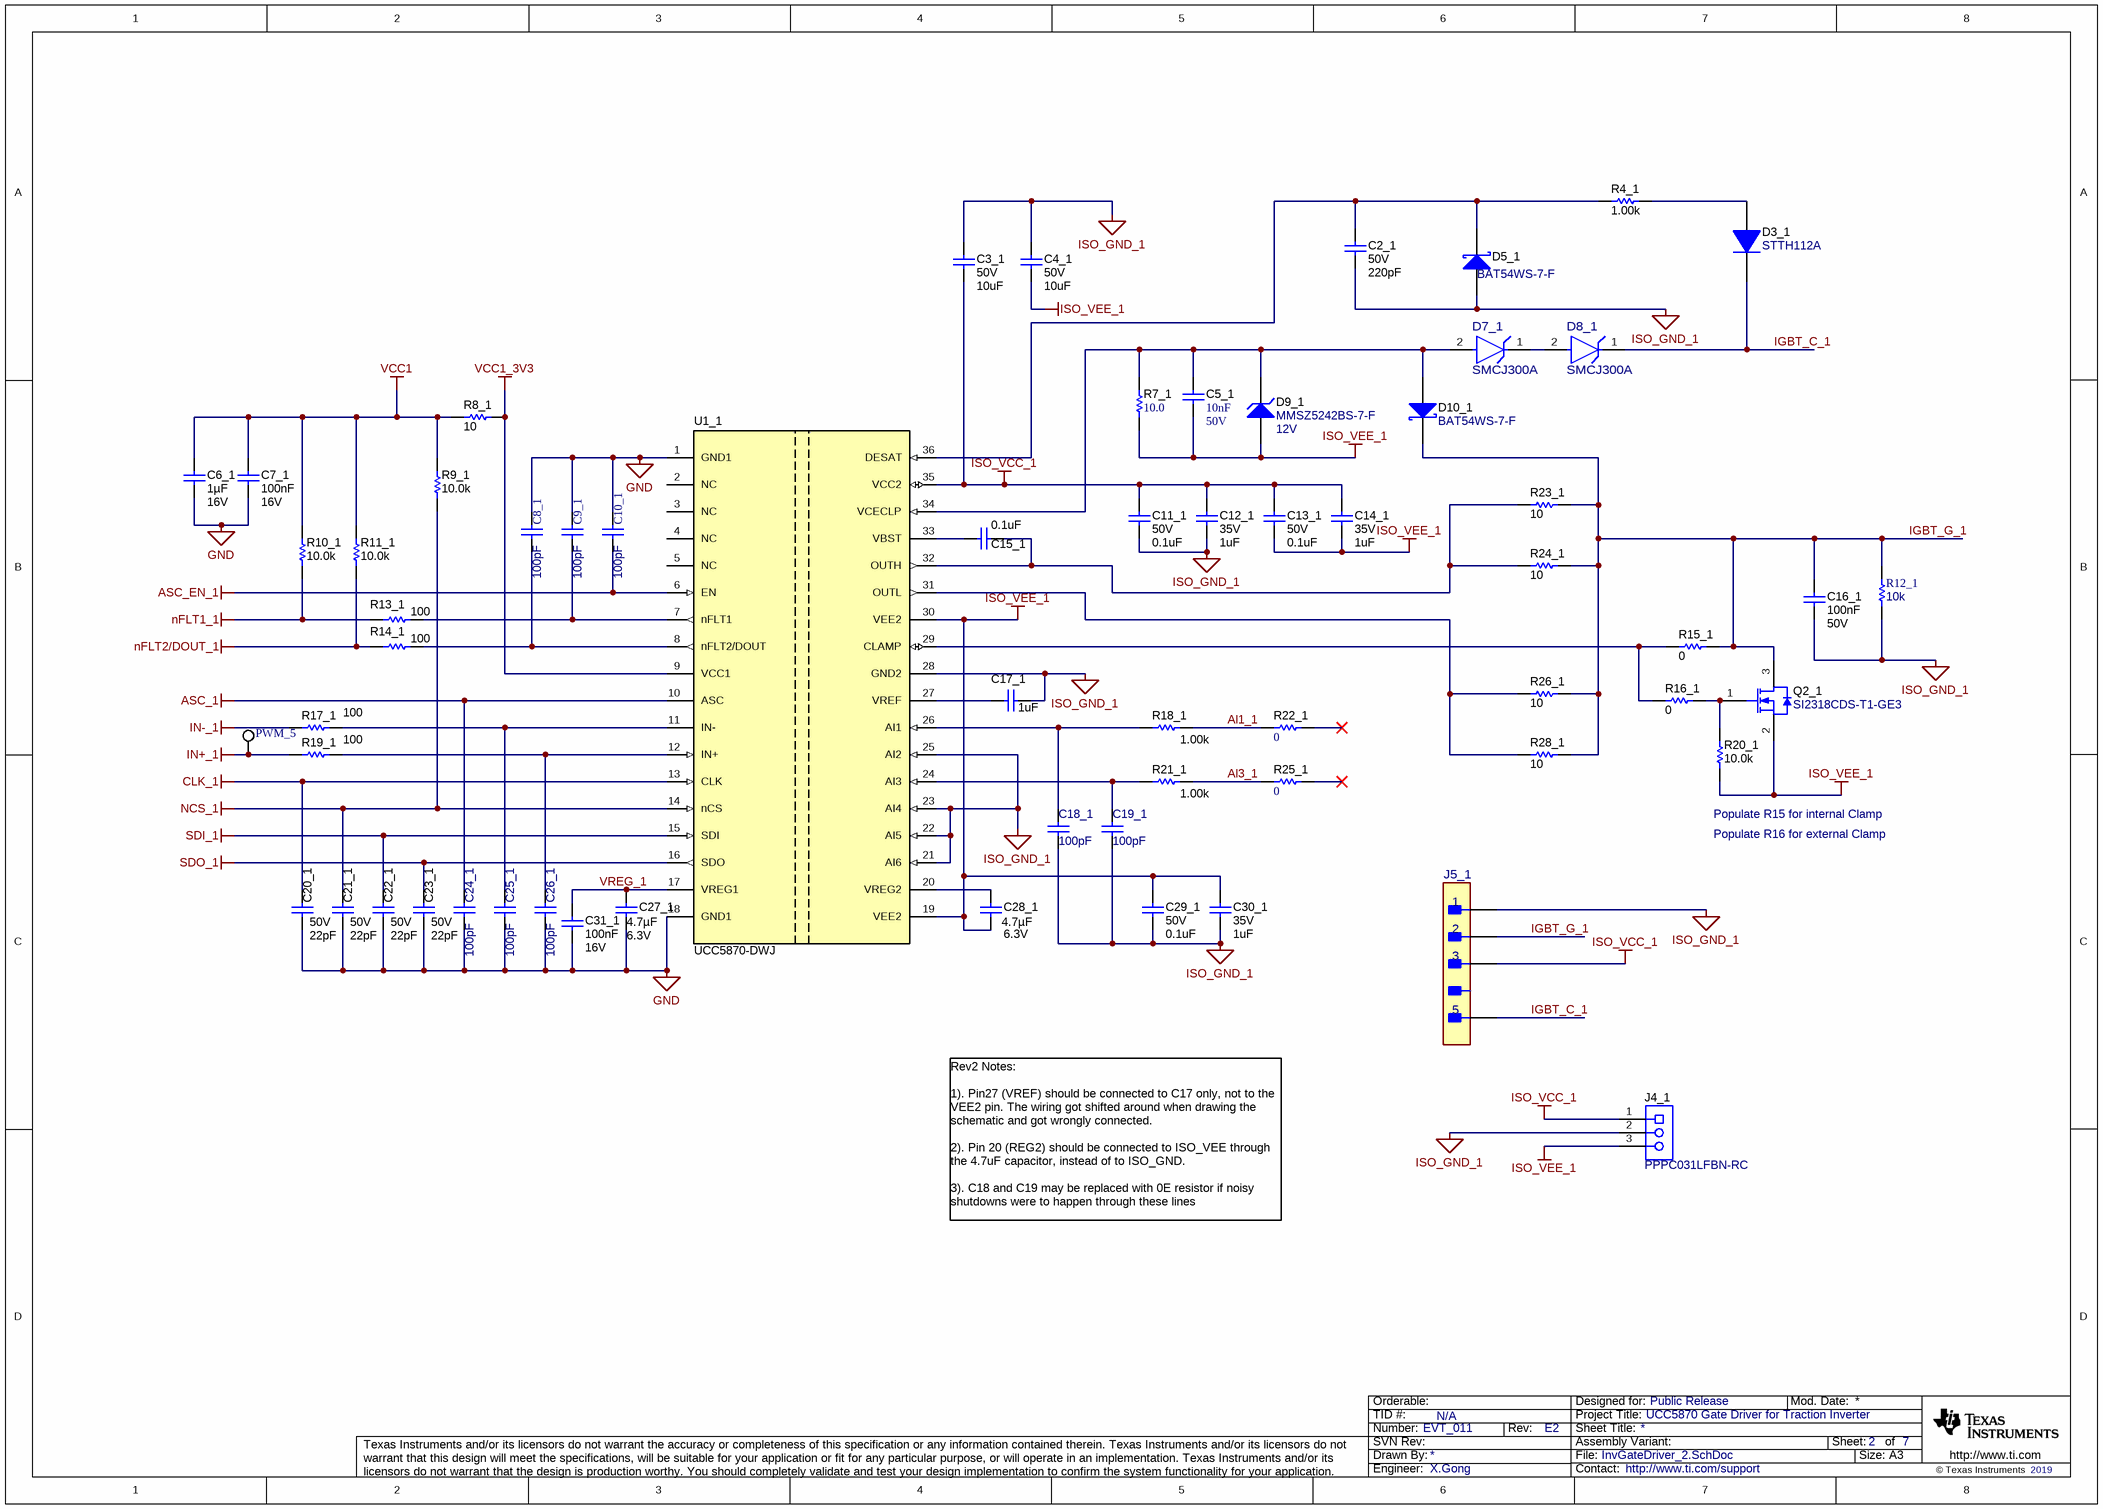
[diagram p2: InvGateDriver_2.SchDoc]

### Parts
C2_1  VDC_V: 50V  ValueDisplayed: 220pF  [0603]  (hidden comment: GRM188R71H221KA01D)
C3_1  VDC_V: 50V  ValueDisplayed: 10uF  [1206_180]  (hidden comment: CL31B106KBHNNNE)
C4_1  VDC_V: 50V  ValueDisplayed: 10uF  [1206_180]  (hidden comment: CL31B106KBHNNNE)
C5_1  Cap_F: 10nF  VDC_V: 50V  [0603]  (hidden comment: GRM188R71H103KA01D)
C6_1  Cap_F: 1µF  VDC_V: 16V  [0603]  (hidden comment: GCM188R71C105MA64D)
C7_1  Cap_F: 100nF  VDC_V: 16V  [0603]  (hidden comment: CGJ3E2X7R1C104K080AA)
C8_1  ValueDisplayed: 100pF  [0603]  (hidden comment: GCM1885C1H101JA16J)
C9_1  ValueDisplayed: 100pF  [0603]  (hidden comment: GCM1885C1H101JA16J)
C10_1  ValueDisplayed: 100pF  [0603]  (hidden comment: GCM1885C1H101JA16J)
C11_1  VDC_V: 50V  ValueDisplayed: 0.1uF  [0603]  (hidden comment: C1608X5R1H104K080AA)
C12_1  VDC_V: 35V  ValueDisplayed: 1uF  [0603]  (hidden comment: CGA3E1X7R1V105K080AC)
C13_1  VDC_V: 50V  ValueDisplayed: 0.1uF  [0603]  (hidden comment: C1608X5R1H104K080AA)
C14_1  VDC_V: 35V  ValueDisplayed: 1uF  [0603]  (hidden comment: CGA3E1X7R1V105K080AC)
C15_1  ValueDisplayed: 0.1uF  [0603]  (hidden comment: C1608X5R1H104K080AA)
C16_1  Cap_F: 100nF  VDC_V: 50V  [0805_HV]  (hidden comment: C0805C104K5RACAUTO)
C17_1  ValueDisplayed: 1uF  [0603]  (hidden comment: CGA3E1X7R1V105K080AC)
C18_1  ValueDisplayed: 100pF  [0603]  (hidden comment: GCM1885C1H101JA16J)
C19_1  ValueDisplayed: 100pF  [0603]  (hidden comment: GCM1885C1H101JA16J)
C20_1  VDC_V: 50V  ValueDisplayed: 22pF  [0603]  (hidden comment: CGA3E2C0G1H220J080AA)
C21_1  VDC_V: 50V  ValueDisplayed: 22pF  [0603]  (hidden comment: CGA3E2C0G1H220J080AA)
C22_1  VDC_V: 50V  ValueDisplayed: 22pF  [0603]  (hidden comment: CGA3E2C0G1H220J080AA)
C23_1  VDC_V: 50V  ValueDisplayed: 22pF  [0603]  (hidden comment: CGA3E2C0G1H220J080AA)
C24_1  ValueDisplayed: 100pF  [0603]  (hidden comment: GCM1885C1H101JA16J)
C25_1  ValueDisplayed: 100pF  [0603]  (hidden comment: GCM1885C1H101JA16J)
C26_1  ValueDisplayed: 100pF  [0603]  (hidden comment: GCM1885C1H101JA16J)
C27_1  Cap_F: 4.7µF  VDC_V: 6.3V  [0603]  (hidden comment: CL10B475KQ8NQND)
C28_1  Cap_F: 4.7µF  VDC_V: 6.3V  [0603]  (hidden comment: CL10B475KQ8NQND)
C29_1  VDC_V: 50V  ValueDisplayed: 0.1uF  [0603]  (hidden comment: C1608X5R1H104K080AA)
C30_1  VDC_V: 35V  ValueDisplayed: 1uF  [0603]  (hidden comment: CGA3E1X7R1V105K080AC)
C31_1  Cap_F: 100nF  VDC_V: 16V  [0603]  (hidden comment: CGJ3E2X7R1C104K080AA)
D3_1  STTH112A  [SMA]
D5_1  BAT54WS-7-F  [SOD-323]
D7_1  SMCJ300A  [FP-SMCJ300A_DO214AB-MFG]
D8_1  SMCJ300A  [FP-SMCJ300A_DO214AB-MFG]
D9_1  MMSZ5242BS-7-F  value 12V  [SOD-323]
D10_1  BAT54WS-7-F  [SOD-323]
J4_1  PPPC031LFBN-RC  [Sullins_PPPC031LFBN-RC]
J5_1  TSW-105-08-G-S-RA-004  [FP-TSW-105-08-G-S-RA-004_HDR4-MFG]  (value not drawn)
PWM_5  5002  [Keystone5002]  (value not drawn)
Q2_1  SI2318CDS-T1-GE3  [SOT-23]
R4_1  ValueDisplayed: 1.00k  [0603]  (hidden comment: CRCW06031K00FKEA)
R7_1  ValueDisplayed: 10.0  [0805_HV]  (hidden comment: CRCW080510R0FKEA)
R8_1  ValueDisplayed: 10  [0805_HV]  (hidden comment: CRCW080510R0JNEA)
R9_1  ValueDisplayed: 10.0k  [0603]  (hidden comment: ERJ-3EKF1002V)
R10_1  ValueDisplayed: 10.0k  [0603]  (hidden comment: ERJ-3EKF1002V)
R11_1  ValueDisplayed: 10.0k  [0603]  (hidden comment: ERJ-3EKF1002V)
R12_1  ValueDisplayed: 10k  [0603]  (hidden comment: CRCW060310K0JNEA)
R13_1  ValueDisplayed: 100  [0603]  (hidden comment: CRCW0603100RJNEA)
R14_1  ValueDisplayed: 100  [0603]  (hidden comment: CRCW0603100RJNEA)
R15_1  ValueDisplayed: 0  [0805_HV]  (hidden comment: CRCW08050000Z0EA)
R16_1  ValueDisplayed: 0  [0805_HV]  (hidden comment: CRCW08050000Z0EA)
R17_1  ValueDisplayed: 100  [0603]  (hidden comment: CRCW0603100RJNEA)
R18_1  ValueDisplayed: 1.00k  [0603]  (hidden comment: CRCW06031K00FKEA)
R19_1  ValueDisplayed: 100  [0603]  (hidden comment: CRCW0603100RJNEA)
R20_1  ValueDisplayed: 10.0k  [0603]  (hidden comment: RCG060310K0FKEA)
R21_1  ValueDisplayed: 1.00k  [0603]  (hidden comment: CRCW06031K00FKEA)
R22_1  ValueDisplayed: 0  [0603]  (hidden comment: CRCW06030000Z0EA)
R23_1  ValueDisplayed: 10  [2010]  (hidden comment: CRCW201010R0JNEF)
R24_1  ValueDisplayed: 10  [2010]  (hidden comment: CRCW201010R0JNEF)
R25_1  ValueDisplayed: 0  [0603]  (hidden comment: CRCW06030000Z0EA)
R26_1  ValueDisplayed: 10  [2010]  (hidden comment: CRCW201010R0JNEF)
R28_1  ValueDisplayed: 10  [2010]  (hidden comment: CRCW201010R0JNEF)
U1_1  UCC5870-DWJ  [DWJ0036A]

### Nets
ASC_1: C24_1.1 U1_1.10(ASC)
ASC_EN_1: C10_1.2 U1_1.6(EN)  [project net ASC_EN]
CLK_1: C20_1.1 U1_1.13(CLK)  [project net CLK]
GND: C6_1.2 C7_1.2 C8_1.1 C9_1.1 C10_1.1 C20_1.2 C21_1.2 C22_1.2 C23_1.2 C24_1.2 C25_1.2 C26_1.2 C27_1.2 C31_1.2 U1_1.1(GND1) U1_1.18(GND1)
IN+_1: PWM_5.1 R19_1.1  [project net IN+_C]
IN-_1: R17_1.1  [project net IN-_C]
ISO_GND_1: C2_1.1 C3_1.1 C4_1.1 C11_1.2 C12_1.2 C16_1.2 C17_1.2 C18_1.2 C19_1.2 C29_1.2 C30_1.1 D5_1.2(A) J4_1.2 J5_1.1 R12_1.1 U1_1.21(AI6) U1_1.22(AI5) U1_1.23(AI4) U1_1.25(AI2) U1_1.28(GND2)
ISO_VCC_1: C3_1.2 C11_1.1 C12_1.1 C13_1.1 C14_1.1 J4_1.1 J5_1.3 U1_1.35(VCC2)
ISO_VEE_1: C4_1.2 C5_1.2 C13_1.2 C14_1.2 C28_1.2 C29_1.1 C30_1.2 D9_1.2(A) J4_1.3 Q2_1.2(S) R7_1.1 R20_1.1 U1_1.19(VEE2) U1_1.30(VEE2)
NCS_1: C21_1.1 R9_1.1 U1_1.14(nCS)  [project net NCS]
nFLT1_1: R10_1.2 R13_1.1
nFLT2/DOUT_1: R11_1.1 R14_1.1
SDI_1: C22_1.1 U1_1.15(SDI)  [project net SDI]
SDO_1: C23_1.1 U1_1.16(SDO)  [project net SDO]
VCC1: C6_1.1 C7_1.1 R8_1.1 R9_1.2 R10_1.1 R11_1.2
VCC1_3V3: R8_1.2 U1_1.9(VCC1)
Al1_1: R18_1.2 R22_1.1
Al3_1: R21_1.2 R25_1.1
IGBT_C_1: D3_1.1(K) D8_1.1(CATHODE) J5_1.5
IGBT_G_1: C16_1.1 D10_1.1(K) J5_1.2 Q2_1.3(D) R12_1.2 R15_1.1 R23_1.2 R24_1.2 R26_1.2 R28_1.2
VREG_1: C27_1.1 C31_1.1 U1_1.17(VREG1)
NetC2_1_2: C2_1.2 D5_1.1(K) R4_1.1 U1_1.36(DESAT)
NetC5_1_1: C5_1.1 D7_1.2(ANODE) D9_1.1(K) D10_1.2(A) R7_1.2 U1_1.34(VCECLP)
NetC8_1_2: C8_1.2 R14_1.2 U1_1.8(nFLT2/DOUT)
NetC9_1_2: C9_1.2 R13_1.2 U1_1.7(nFLT1)
NetC15_1_1: C15_1.1 U1_1.33(VBST)
NetC15_1_2: C15_1.2 R23_1.1 R24_1.1 U1_1.32(OUTH)
NetC17_1_1: C17_1.1 U1_1.27(VREF)
NetC18_1_1: C18_1.1 R18_1.1 U1_1.26(AI1)
NetC19_1_1: C19_1.1 R21_1.1 U1_1.24(AI3)
NetC25_1_1: C25_1.1 R17_1.2 U1_1.11(IN-)
NetC26_1_1: C26_1.1 R19_1.2 U1_1.12(IN+)
NetC28_1_1: C28_1.1 U1_1.20(VREG2)
NetD3_1_2: D3_1.2(A) R4_1.2
NetD7_1_1: D7_1.1(CATHODE) D8_1.2(ANODE)
NetQ2_1_1: Q2_1.1(G) R16_1.1 R20_1.2
NetR15_1_2: R15_1.2 R16_1.2 U1_1.29(CLAMP)
NetR26_1_1: R26_1.1 R28_1.1 U1_1.31(OUTL)

Not connected (* = marked no-connect by the designer): R22_1 2*; R25_1 2*; U1_1 2(NC) 3(NC) 4(NC) 5(NC)

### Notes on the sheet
- (near R20_1) Populate R15 for internal Clamp
- Populate R16 for external Clamp
- Rev2 Notes:
  1). Pin27 (VREF) should be connected to C17 only, not to the VEE2 pin. The wiring got shifted around when drawing the schematic and got wrongly connected.
  2). Pin 20 (REG2) should be connected to ISO_VEE through the 4.7uF capacitor, instead of to ISO_GND.
  3). C18 and C19 may be replaced with 0E resistor if noisy shutdowns were to happen through these lines

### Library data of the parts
C2_1 = CMP-0007442-5: as C2 on sheet InvGateDriver_1
C3_1 = CMP-0008802-2: as C3 on sheet InvGateDriver_1
C4_1 = CMP-0008802-2: as C4 on sheet InvGateDriver_1
C5_1 = CMP-0007433-4: as C5 on sheet InvGateDriver_1
C6_1 = CMP-0007137-5: as C6 on sheet InvGateDriver_1
C7_1 = CMP-0007106-4: as C7 on sheet InvGateDriver_1
C8_1 C9_1 C10_1 C18_1 C19_1 C24_1 C25_1 C26_1 = CMP-0750041-1: as C8 on sheet InvGateDriver_1
C11_1 C29_1 = CMP-0007010-5: as C11 on sheet InvGateDriver_1
C12_1 C14_1 C30_1 = CMP-0007067-4: as C12 on sheet InvGateDriver_1
C13_1 = CMP-0007010-5: as C13 on sheet InvGateDriver_1
C15_1 = CMP-0007010-5: as C15 on sheet InvGateDriver_1
C16_1 = CMP-0007725-2: as C16 on sheet InvGateDriver_1
C17_1 = CMP-0007067-4: as C17 on sheet InvGateDriver_1
C20_1 C21_1 C22_1 C23_1 = CMP-0007071-3: as C20 on sheet InvGateDriver_1
C27_1 C28_1 = CMP-0007112-4: as C27 on sheet InvGateDriver_1
C31_1 = CMP-0007106-4: as C31 on sheet InvGateDriver_1
D3_1 = CMP-0077081-2: as D3 on sheet InvGateDriver_1
D5_1 D10_1 = CMP-0028458-2: as D5 on sheet InvGateDriver_1
D7_1 D8_1 = CMP-0088475-1: as D7 on sheet InvGateDriver_1
D9_1 = CMP-0005831-4: as D9 on sheet InvGateDriver_1
J4_1 = CMP-0054646-1: as J4 on sheet InvGateDriver_1
J5_1 = CMP-0088430-1: as J5 on sheet InvGateDriver_1
PWM_5 = CMP-0055139-1: as PWM_6 on sheet InvGateDriver_1
Q2_1 = CMP-0000739-1: as Q2 on sheet InvGateDriver_1
R4_1 R18_1 R21_1 = CMP-0022109-5: as R4 on sheet InvGateDriver_1
R7_1 = CMP-0020847-3: as R7 on sheet InvGateDriver_1
R8_1 = CRCW080510R0JNEA: as R8 on sheet InvGateDriver_1
R9_1 R10_1 R11_1 = CMP-0022684-3: as R9 on sheet InvGateDriver_1
R12_1 = CMP-0025701-4: as R2 on sheet Hardware and Connector_r1
R13_1 R14_1 R17_1 R19_1 = CMP-0025700-4: as R13 on sheet InvGateDriver_1
R15_1 R16_1 = CRCW08050000Z0EA: as R15 on sheet InvGateDriver_1
R20_1 = RCG060310K0FKEA: as R20 on sheet InvGateDriver_1
R22_1 R25_1 = CMP-0025697-4: as R22 on sheet InvGateDriver_1
R23_1 R24_1 R26_1 R28_1 = CRCW201010R0JNEF: as R23 on sheet InvGateDriver_1
U1_1 = CMP-0080759-3: as U1 on sheet InvGateDriver_1

## Sheet InvGateDriver_3.SchDoc
size A3; SheetNumber: 3; SheetTotal: 7; PageSetup: Record=PageOptions¦CenterHorizontal=True¦CenterVertical=True¦PrintScale=0.69¦XCorrection=1.00¦YCorrection=1.00¦PrintKind=0¦BorderSize=5000000¦LeftOffset=0¦BottomOffset=0¦Orientation=2¦PaperLength=1000¦PaperWidth=1000¦Scale=100¦PaperSource=15¦PrintQuality=600¦MediaType=1¦DitherType=10¦PaperKind=Letter¦PrintScaleMode=1
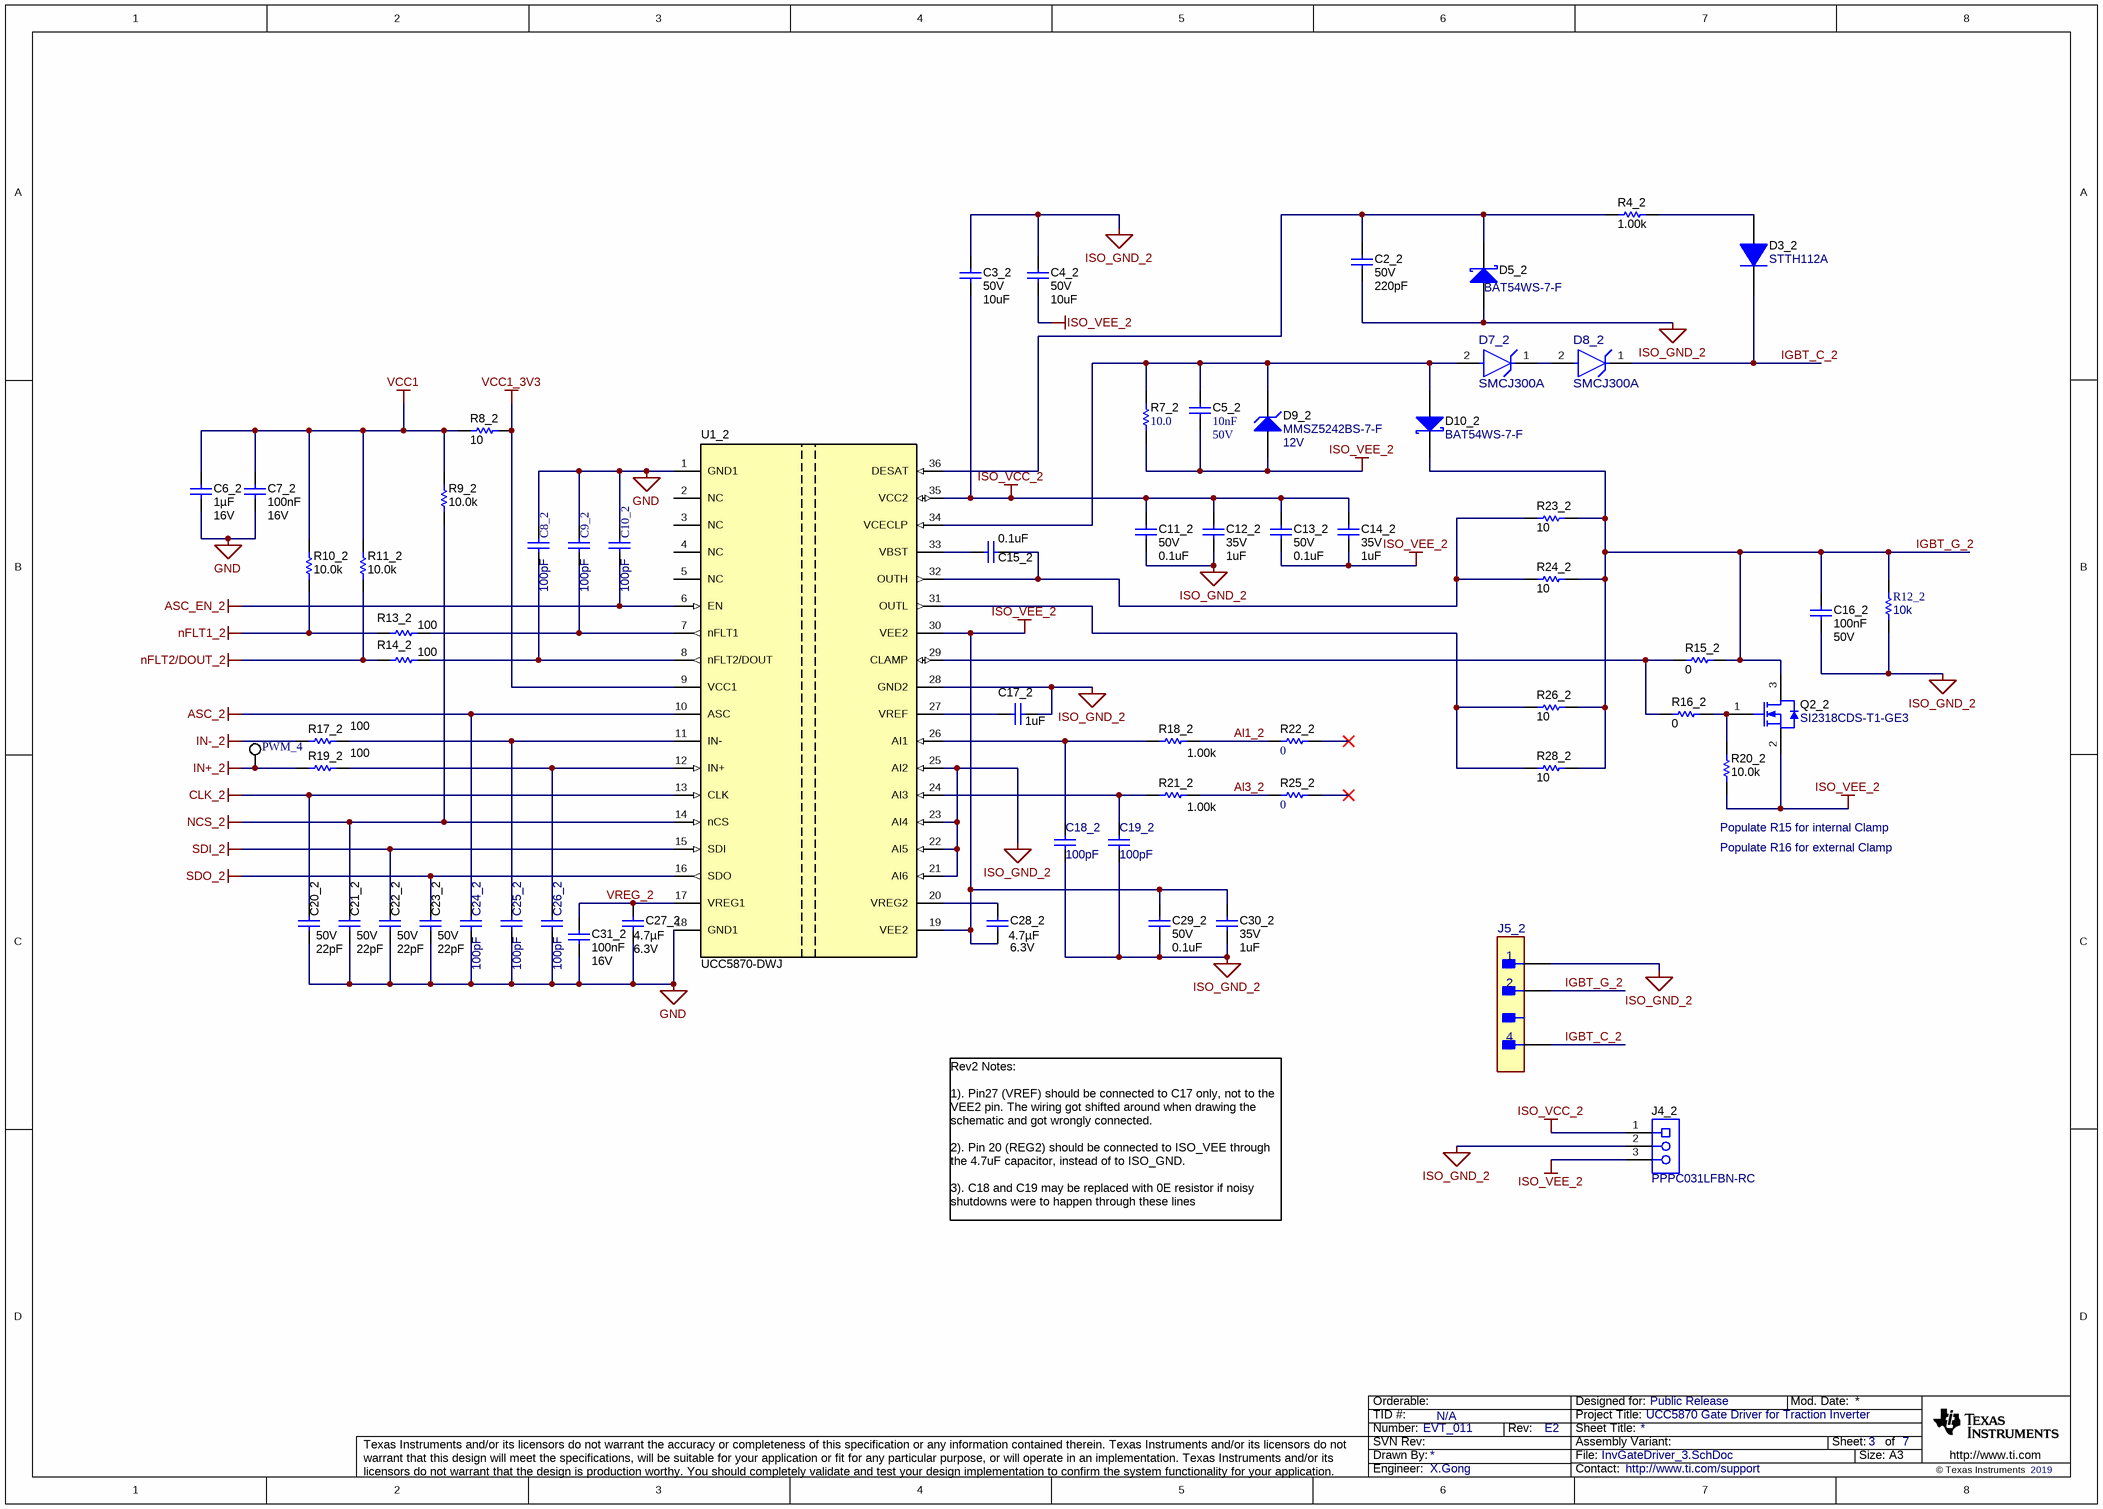
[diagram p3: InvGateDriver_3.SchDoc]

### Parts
C2_2  VDC_V: 50V  ValueDisplayed: 220pF  [0603]  (hidden comment: GRM188R71H221KA01D)
C3_2  VDC_V: 50V  ValueDisplayed: 10uF  [1206_180]  (hidden comment: CL31B106KBHNNNE)
C4_2  VDC_V: 50V  ValueDisplayed: 10uF  [1206_180]  (hidden comment: CL31B106KBHNNNE)
C5_2  Cap_F: 10nF  VDC_V: 50V  [0603]  (hidden comment: GRM188R71H103KA01D)
C6_2  Cap_F: 1µF  VDC_V: 16V  [0603]  (hidden comment: GCM188R71C105MA64D)
C7_2  Cap_F: 100nF  VDC_V: 16V  [0603]  (hidden comment: CGJ3E2X7R1C104K080AA)
C8_2  ValueDisplayed: 100pF  [0603]  (hidden comment: GCM1885C1H101JA16J)
C9_2  ValueDisplayed: 100pF  [0603]  (hidden comment: GCM1885C1H101JA16J)
C10_2  ValueDisplayed: 100pF  [0603]  (hidden comment: GCM1885C1H101JA16J)
C11_2  VDC_V: 50V  ValueDisplayed: 0.1uF  [0603]  (hidden comment: C1608X5R1H104K080AA)
C12_2  VDC_V: 35V  ValueDisplayed: 1uF  [0603]  (hidden comment: CGA3E1X7R1V105K080AC)
C13_2  VDC_V: 50V  ValueDisplayed: 0.1uF  [0603]  (hidden comment: C1608X5R1H104K080AA)
C14_2  VDC_V: 35V  ValueDisplayed: 1uF  [0603]  (hidden comment: CGA3E1X7R1V105K080AC)
C15_2  ValueDisplayed: 0.1uF  [0603]  (hidden comment: C1608X5R1H104K080AA)
C16_2  Cap_F: 100nF  VDC_V: 50V  [0805_HV]  (hidden comment: C0805C104K5RACAUTO)
C17_2  ValueDisplayed: 1uF  [0603]  (hidden comment: CGA3E1X7R1V105K080AC)
C18_2  ValueDisplayed: 100pF  [0603]  (hidden comment: GCM1885C1H101JA16J)
C19_2  ValueDisplayed: 100pF  [0603]  (hidden comment: GCM1885C1H101JA16J)
C20_2  VDC_V: 50V  ValueDisplayed: 22pF  [0603]  (hidden comment: CGA3E2C0G1H220J080AA)
C21_2  VDC_V: 50V  ValueDisplayed: 22pF  [0603]  (hidden comment: CGA3E2C0G1H220J080AA)
C22_2  VDC_V: 50V  ValueDisplayed: 22pF  [0603]  (hidden comment: CGA3E2C0G1H220J080AA)
C23_2  VDC_V: 50V  ValueDisplayed: 22pF  [0603]  (hidden comment: CGA3E2C0G1H220J080AA)
C24_2  ValueDisplayed: 100pF  [0603]  (hidden comment: GCM1885C1H101JA16J)
C25_2  ValueDisplayed: 100pF  [0603]  (hidden comment: GCM1885C1H101JA16J)
C26_2  ValueDisplayed: 100pF  [0603]  (hidden comment: GCM1885C1H101JA16J)
C27_2  Cap_F: 4.7µF  VDC_V: 6.3V  [0603]  (hidden comment: CL10B475KQ8NQND)
C28_2  Cap_F: 4.7µF  VDC_V: 6.3V  [0603]  (hidden comment: CL10B475KQ8NQND)
C29_2  VDC_V: 50V  ValueDisplayed: 0.1uF  [0603]  (hidden comment: C1608X5R1H104K080AA)
C30_2  VDC_V: 35V  ValueDisplayed: 1uF  [0603]  (hidden comment: CGA3E1X7R1V105K080AC)
C31_2  Cap_F: 100nF  VDC_V: 16V  [0603]  (hidden comment: CGJ3E2X7R1C104K080AA)
D3_2  STTH112A  [SMA]
D5_2  BAT54WS-7-F  [SOD-323]
D7_2  SMCJ300A  [FP-SMCJ300A_DO214AB-MFG]
D8_2  SMCJ300A  [FP-SMCJ300A_DO214AB-MFG]
D9_2  MMSZ5242BS-7-F  value 12V  [SOD-323]
D10_2  BAT54WS-7-F  [SOD-323]
J4_2  PPPC031LFBN-RC  [Sullins_PPPC031LFBN-RC]
J5_2  TSW-104-08-G-S-RA-003  [FP-TSW-104-08-G-S-RA-003_HDR3-MFG]  (value not drawn)
PWM_4  5002  [Keystone5002]  (value not drawn)
Q2_2  SI2318CDS-T1-GE3  [SOT-23]
R4_2  ValueDisplayed: 1.00k  [0603]  (hidden comment: CRCW06031K00FKEA)
R7_2  ValueDisplayed: 10.0  [0805_HV]  (hidden comment: CRCW080510R0FKEA)
R8_2  ValueDisplayed: 10  [0805_HV]  (hidden comment: CRCW080510R0JNEA)
R9_2  ValueDisplayed: 10.0k  [0603]  (hidden comment: ERJ-3EKF1002V)
R10_2  ValueDisplayed: 10.0k  [0603]  (hidden comment: ERJ-3EKF1002V)
R11_2  ValueDisplayed: 10.0k  [0603]  (hidden comment: ERJ-3EKF1002V)
R12_2  ValueDisplayed: 10k  [0603]  (hidden comment: CRCW060310K0JNEA)
R13_2  ValueDisplayed: 100  [0603]  (hidden comment: CRCW0603100RJNEA)
R14_2  ValueDisplayed: 100  [0603]  (hidden comment: CRCW0603100RJNEA)
R15_2  ValueDisplayed: 0  [0805_HV]  (hidden comment: CRCW08050000Z0EA)
R16_2  ValueDisplayed: 0  [0805_HV]  (hidden comment: CRCW08050000Z0EA)
R17_2  ValueDisplayed: 100  [0603]  (hidden comment: CRCW0603100RJNEA)
R18_2  ValueDisplayed: 1.00k  [0603]  (hidden comment: CRCW06031K00FKEA)
R19_2  ValueDisplayed: 100  [0603]  (hidden comment: CRCW0603100RJNEA)
R20_2  ValueDisplayed: 10.0k  [0603]  (hidden comment: RCG060310K0FKEA)
R21_2  ValueDisplayed: 1.00k  [0603]  (hidden comment: CRCW06031K00FKEA)
R22_2  ValueDisplayed: 0  [0603]  (hidden comment: CRCW06030000Z0EA)
R23_2  ValueDisplayed: 10  [2010]  (hidden comment: CRCW201010R0JNEF)
R24_2  ValueDisplayed: 10  [2010]  (hidden comment: CRCW201010R0JNEF)
R25_2  ValueDisplayed: 0  [0603]  (hidden comment: CRCW06030000Z0EA)
R26_2  ValueDisplayed: 10  [2010]  (hidden comment: CRCW201010R0JNEF)
R28_2  ValueDisplayed: 10  [2010]  (hidden comment: CRCW201010R0JNEF)
U1_2  UCC5870-DWJ  [DWJ0036A]

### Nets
ASC_2: C24_2.1 U1_2.10(ASC)  [project net ASC]
ASC_EN_2: C10_2.2 U1_2.6(EN)  [project net ASC_EN]
CLK_2: C20_2.1 U1_2.13(CLK)  [project net CLK]
GND: C6_2.2 C7_2.2 C8_2.1 C9_2.1 C10_2.1 C20_2.2 C21_2.2 C22_2.2 C23_2.2 C24_2.2 C25_2.2 C26_2.2 C27_2.2 C31_2.2 U1_2.1(GND1) U1_2.18(GND1)
IN+_2: PWM_4.1 R19_2.1  [project net IN-_B]
IN-_2: R17_2.1  [project net IN+_B]
ISO_GND_2: C2_2.1 C3_2.1 C4_2.1 C11_2.2 C12_2.2 C16_2.2 C17_2.2 C18_2.2 C19_2.2 C29_2.2 C30_2.1 D5_2.2(A) J4_2.2 J5_2.1 R12_2.1 U1_2.21(AI6) U1_2.22(AI5) U1_2.23(AI4) U1_2.25(AI2) U1_2.28(GND2)
ISO_VCC_2: C3_2.2 C11_2.1 C12_2.1 C13_2.1 C14_2.1 J4_2.1 U1_2.35(VCC2)
ISO_VEE_2: C4_2.2 C5_2.2 C13_2.2 C14_2.2 C28_2.2 C29_2.1 C30_2.2 D9_2.2(A) J4_2.3 Q2_2.2(S) R7_2.1 R20_2.1 U1_2.19(VEE2) U1_2.30(VEE2)
NCS_2: C21_2.1 R9_2.1 U1_2.14(nCS)  [project net NCS]
nFLT1_2: R10_2.2 R13_2.1  [project net nFLT1]
nFLT2/DOUT_2: R11_2.1 R14_2.1  [project net nFLT2/DOUT]
SDI_2: C22_2.1 U1_2.15(SDI)  [project net SDI]
SDO_2: C23_2.1 U1_2.16(SDO)  [project net SDO]
VCC1: C6_2.1 C7_2.1 R8_2.1 R9_2.2 R10_2.1 R11_2.2
VCC1_3V3: R8_2.2 U1_2.9(VCC1)
Al1_2: R18_2.2 R22_2.1
Al3_2: R21_2.2 R25_2.1
IGBT_C_2: D3_2.1(K) D8_2.1(CATHODE) J5_2.4
IGBT_G_2: C16_2.1 D10_2.1(K) J5_2.2 Q2_2.3(D) R12_2.2 R15_2.1 R23_2.2 R24_2.2 R26_2.2 R28_2.2
VREG_2: C27_2.1 C31_2.1 U1_2.17(VREG1)
NetC2_2_2: C2_2.2 D5_2.1(K) R4_2.1 U1_2.36(DESAT)
NetC5_2_1: C5_2.1 D7_2.2(ANODE) D9_2.1(K) D10_2.2(A) R7_2.2 U1_2.34(VCECLP)
NetC8_2_2: C8_2.2 R14_2.2 U1_2.8(nFLT2/DOUT)
NetC9_2_2: C9_2.2 R13_2.2 U1_2.7(nFLT1)
NetC15_2_1: C15_2.1 U1_2.33(VBST)
NetC15_2_2: C15_2.2 R23_2.1 R24_2.1 U1_2.32(OUTH)
NetC17_2_1: C17_2.1 U1_2.27(VREF)
NetC18_2_1: C18_2.1 R18_2.1 U1_2.26(AI1)
NetC19_2_1: C19_2.1 R21_2.1 U1_2.24(AI3)
NetC25_2_1: C25_2.1 R17_2.2 U1_2.11(IN-)
NetC26_2_1: C26_2.1 R19_2.2 U1_2.12(IN+)
NetC28_2_1: C28_2.1 U1_2.20(VREG2)
NetD3_2_2: D3_2.2(A) R4_2.2
NetD7_2_1: D7_2.1(CATHODE) D8_2.2(ANODE)
NetQ2_2_1: Q2_2.1(G) R16_2.1 R20_2.2
NetR15_2_2: R15_2.2 R16_2.2 U1_2.29(CLAMP)
NetR26_2_1: R26_2.1 R28_2.1 U1_2.31(OUTL)

Not connected (* = marked no-connect by the designer): R22_2 2*; R25_2 2*; U1_2 2(NC) 3(NC) 4(NC) 5(NC)

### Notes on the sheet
- (near R20_2) Populate R15 for internal Clamp
- Populate R16 for external Clamp
- Rev2 Notes:
  1). Pin27 (VREF) should be connected to C17 only, not to the VEE2 pin. The wiring got shifted around when drawing the schematic and got wrongly connected.
  2). Pin 20 (REG2) should be connected to ISO_VEE through the 4.7uF capacitor, instead of to ISO_GND.
  3). C18 and C19 may be replaced with 0E resistor if noisy shutdowns were to happen through these lines

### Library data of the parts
C2_2 = CMP-0007442-5: as C2 on sheet InvGateDriver_1
C3_2 = CMP-0008802-2: as C3 on sheet InvGateDriver_1
C4_2 = CMP-0008802-2: as C4 on sheet InvGateDriver_1
C5_2 = CMP-0007433-4: as C5 on sheet InvGateDriver_1
C6_2 = CMP-0007137-5: as C6 on sheet InvGateDriver_1
C7_2 = CMP-0007106-4: as C7 on sheet InvGateDriver_1
C8_2 C9_2 C10_2 C18_2 C19_2 C24_2 C25_2 C26_2 = CMP-0750041-1: as C8 on sheet InvGateDriver_1
C11_2 C29_2 = CMP-0007010-5: as C11 on sheet InvGateDriver_1
C12_2 C14_2 C30_2 = CMP-0007067-4: as C12 on sheet InvGateDriver_1
C13_2 = CMP-0007010-5: as C13 on sheet InvGateDriver_1
C15_2 = CMP-0007010-5: as C15 on sheet InvGateDriver_1
C16_2 = CMP-0007725-2: as C16 on sheet InvGateDriver_1
C17_2 = CMP-0007067-4: as C17 on sheet InvGateDriver_1
C20_2 C21_2 C22_2 C23_2 = CMP-0007071-3: as C20 on sheet InvGateDriver_1
C27_2 C28_2 = CMP-0007112-4: as C27 on sheet InvGateDriver_1
C31_2 = CMP-0007106-4: as C31 on sheet InvGateDriver_1
D3_2 = CMP-0077081-2: as D3 on sheet InvGateDriver_1
D5_2 D10_2 = CMP-0028458-2: as D5 on sheet InvGateDriver_1
D7_2 D8_2 = CMP-0088475-1: as D7 on sheet InvGateDriver_1
D9_2 = CMP-0005831-4: as D9 on sheet InvGateDriver_1
J4_2 = CMP-0054646-1: as J4 on sheet InvGateDriver_1
J5_2 = CMP-0088429-1: Conn Unshrouded Header HDR 4 POS 2.54mm Solder RA Thru-Hole Automotive Bulk; Manufacturer: Samtec; Conn Orientation: Right Angle; SizeZ_mm: 3.15mm; Voltage_V: 550V; Row_Count: 1; AEC Qualified: No; ContactFinish: Gold,Nickel; Conn Gender: Male
PWM_4 = CMP-0055139-1: as PWM_6 on sheet InvGateDriver_1
Q2_2 = CMP-0000739-1: as Q2 on sheet InvGateDriver_1
R4_2 R18_2 R21_2 = CMP-0022109-5: as R4 on sheet InvGateDriver_1
R7_2 = CMP-0020847-3: as R7 on sheet InvGateDriver_1
R8_2 = CRCW080510R0JNEA: as R8 on sheet InvGateDriver_1
R9_2 R10_2 R11_2 = CMP-0022684-3: as R9 on sheet InvGateDriver_1
R12_2 = CMP-0025701-4: as R2 on sheet Hardware and Connector_r1
R13_2 R14_2 R17_2 R19_2 = CMP-0025700-4: as R13 on sheet InvGateDriver_1
R15_2 R16_2 = CRCW08050000Z0EA: as R15 on sheet InvGateDriver_1
R20_2 = RCG060310K0FKEA: as R20 on sheet InvGateDriver_1
R22_2 R25_2 = CMP-0025697-4: as R22 on sheet InvGateDriver_1
R23_2 R24_2 R26_2 R28_2 = CRCW201010R0JNEF: as R23 on sheet InvGateDriver_1
U1_2 = CMP-0080759-3: as U1 on sheet InvGateDriver_1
